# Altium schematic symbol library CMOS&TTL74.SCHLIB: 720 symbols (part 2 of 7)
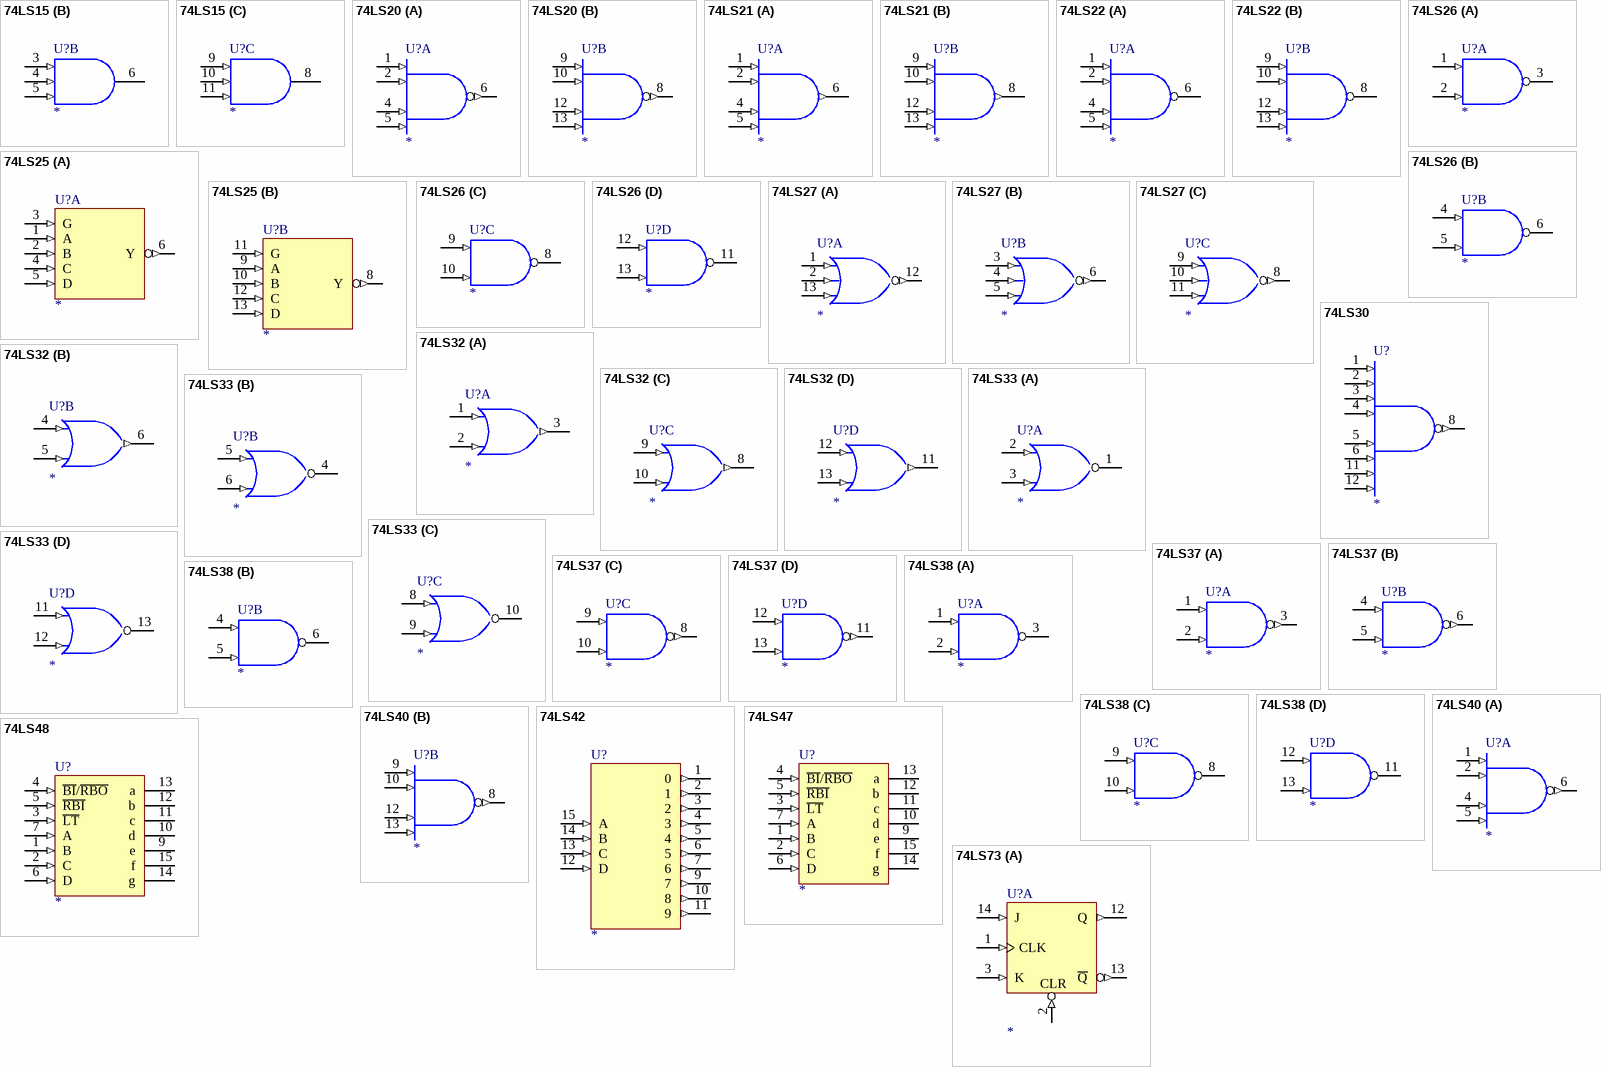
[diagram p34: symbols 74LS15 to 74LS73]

## 74LS30
designator U?
8-Input Positive-NAND Gate
footprint DIP-14
simulation model 74LS30 (SIMCODE)
pins: 1 A (in), 2 B (in), 3 C (in), 4 D (in), 5 E (in), 6 F (in), 7 GND (power) hidden to GND, 8 Y (out), 11 G (in), 12 H (in), 14 VCC (power) hidden to VCC
1 alternate drawing of the same symbol

## 74LS32
designator U?
Quad 2-Input Positive-OR Gate
footprint DIP-14
simulation model 74LS32 (SIMCODE)
part A pins: 1 A (in), 2 B (in), 3 Y (out), 7 GND (power) hidden to GND, 14 VCC (power) hidden to VCC
part B pins: 4 A (in), 5 B (in), 6 Y (out), 7 GND (power) hidden to GND, 14 VCC (power) hidden to VCC
part C pins: 7 GND (power) hidden to GND, 8 Y (out), 9 A (in), 10 B (in), 14 VCC (power) hidden to VCC
part D pins: 7 GND (power) hidden to GND, 11 Y (out), 12 A (in), 13 B (in), 14 VCC (power) hidden to VCC
1 alternate drawing of the same symbol

## 74LS33
designator U?
Quad 2-Input Positive-NOR Buffer with Open-Collector Output
footprint DIP-14
simulation model 74LS33 (SIMCODE)
part A pins: 1 Y (oc), 2 A (in), 3 B (in), 7 GND (power) hidden to GND, 14 VCC (power) hidden to VCC
part B pins: 4 Y (oc), 5 A (in), 6 B (in), 7 GND (power) hidden to GND, 14 VCC (power) hidden to VCC
part C pins: 7 GND (power) hidden to GND, 8 A (in), 9 B (in), 10 Y (oc), 14 VCC (power) hidden to VCC
part D pins: 7 GND (power) hidden to GND, 11 A (in), 12 B (in), 13 Y (oc), 14 VCC (power) hidden to VCC
1 alternate drawing of the same symbol

## 74LS37
designator U?
Quad 2-Input Positive-NAND Buffer
footprint DIP-14
simulation model 74LS37 (SIMCODE)
part A pins: 1 A (in), 2 B (in), 3 Y (out), 7 GND (power) hidden to GND, 14 VCC (power) hidden to VCC
part B pins: 4 A (in), 5 B (in), 6 Y (out), 7 GND (power) hidden to GND, 14 VCC (power) hidden to VCC
part C pins: 7 GND (power) hidden to GND, 8 Y (out), 9 A (in), 10 B (in), 14 VCC (power) hidden to VCC
part D pins: 7 GND (power) hidden to GND, 11 Y (out), 12 A (in), 13 B (in), 14 VCC (power) hidden to VCC
1 alternate drawing of the same symbol

## 74LS38
designator U?
Quad 2-Input Positive-NAND Buffer with Open-Collector Output
footprint DIP-14
simulation model 74LS38 (SIMCODE)
part A pins: 1 A (in), 2 B (in), 3 Y (oc), 7 GND (power) hidden to GND, 14 VCC (power) hidden to VCC
part B pins: 4 A (in), 5 B (in), 6 Y (oc), 7 GND (power) hidden to GND, 14 VCC (power) hidden to VCC
part C pins: 7 GND (power) hidden to GND, 8 Y (oc), 9 A (in), 10 B (in), 14 VCC (power) hidden to VCC
part D pins: 7 GND (power) hidden to GND, 11 Y (oc), 12 A (in), 13 B (in), 14 VCC (power) hidden to VCC
1 alternate drawing of the same symbol

## 74LS40
designator U?
Dual 4-Input Positive-NAND Buffer
footprint DIP-14
simulation model 74LS40 (SIMCODE)
part A pins: 1 A (in), 2 B (in), 4 C (in), 5 D (in), 6 Y (out), 7 GND (power) hidden to GND, 14 VCC (power) hidden to VCC
part B pins: 7 GND (power) hidden to GND, 8 Y (out), 9 A (in), 10 B (in), 12 C (in), 13 D (in), 14 VCC (power) hidden to VCC
2 alternate drawings of the same symbol

## 74LS42
designator U?
4-Line BCD to 10-Line Decimal Decoder
footprint DIP-16
simulation model 74LS42 (SIMCODE)
pins: 1 0 (out), 2 1 (out), 3 2 (out), 4 3 (out), 5 4 (out), 6 5 (out), 7 6 (out), 8 GND (power) hidden to GND, 9 7 (out), 10 8 (out), 11 9 (out), 12 D (in), 13 C (in), 14 B (in), 15 A (in), 16 VCC (power) hidden to VCC
1 alternate drawing of the same symbol

## 74LS47
designator U?
BCD-to-Seven-Segment Decoder/Driver
footprint DIP-16
simulation model 74LS47 (SIMCODE)
pins: 1 B (in), 2 C (in), 3 ~{LT} (in), 4 ~{BI}/~{RBO} (in), 5 ~{RBI} (in), 6 D (in), 7 A (in), 8 GND (power) hidden to GND, 9 e (oc), 10 d (oc), 11 c (oc), 12 b (oc), 13 a (oc), 14 g (oc), 15 f (oc), 16 VCC (power) hidden to VCC
1 alternate drawing of the same symbol

## 74LS48
designator U?
BCD-to-Seven-Segment Decoder/Driver
footprint DIP-16
simulation model 74LS48 (SIMCODE)
pins: 1 B (in), 2 C (in), 3 ~{LT} (in), 4 ~{BI}/~{RBO} (in), 5 ~{RBI} (in), 6 D (in), 7 A (in), 8 GND (power) hidden to GND, 9 e (oc), 10 d (oc), 11 c (oc), 12 b (oc), 13 a (oc), 14 g (oc), 15 f (oc), 16 VCC (power) hidden to VCC
1 alternate drawing of the same symbol

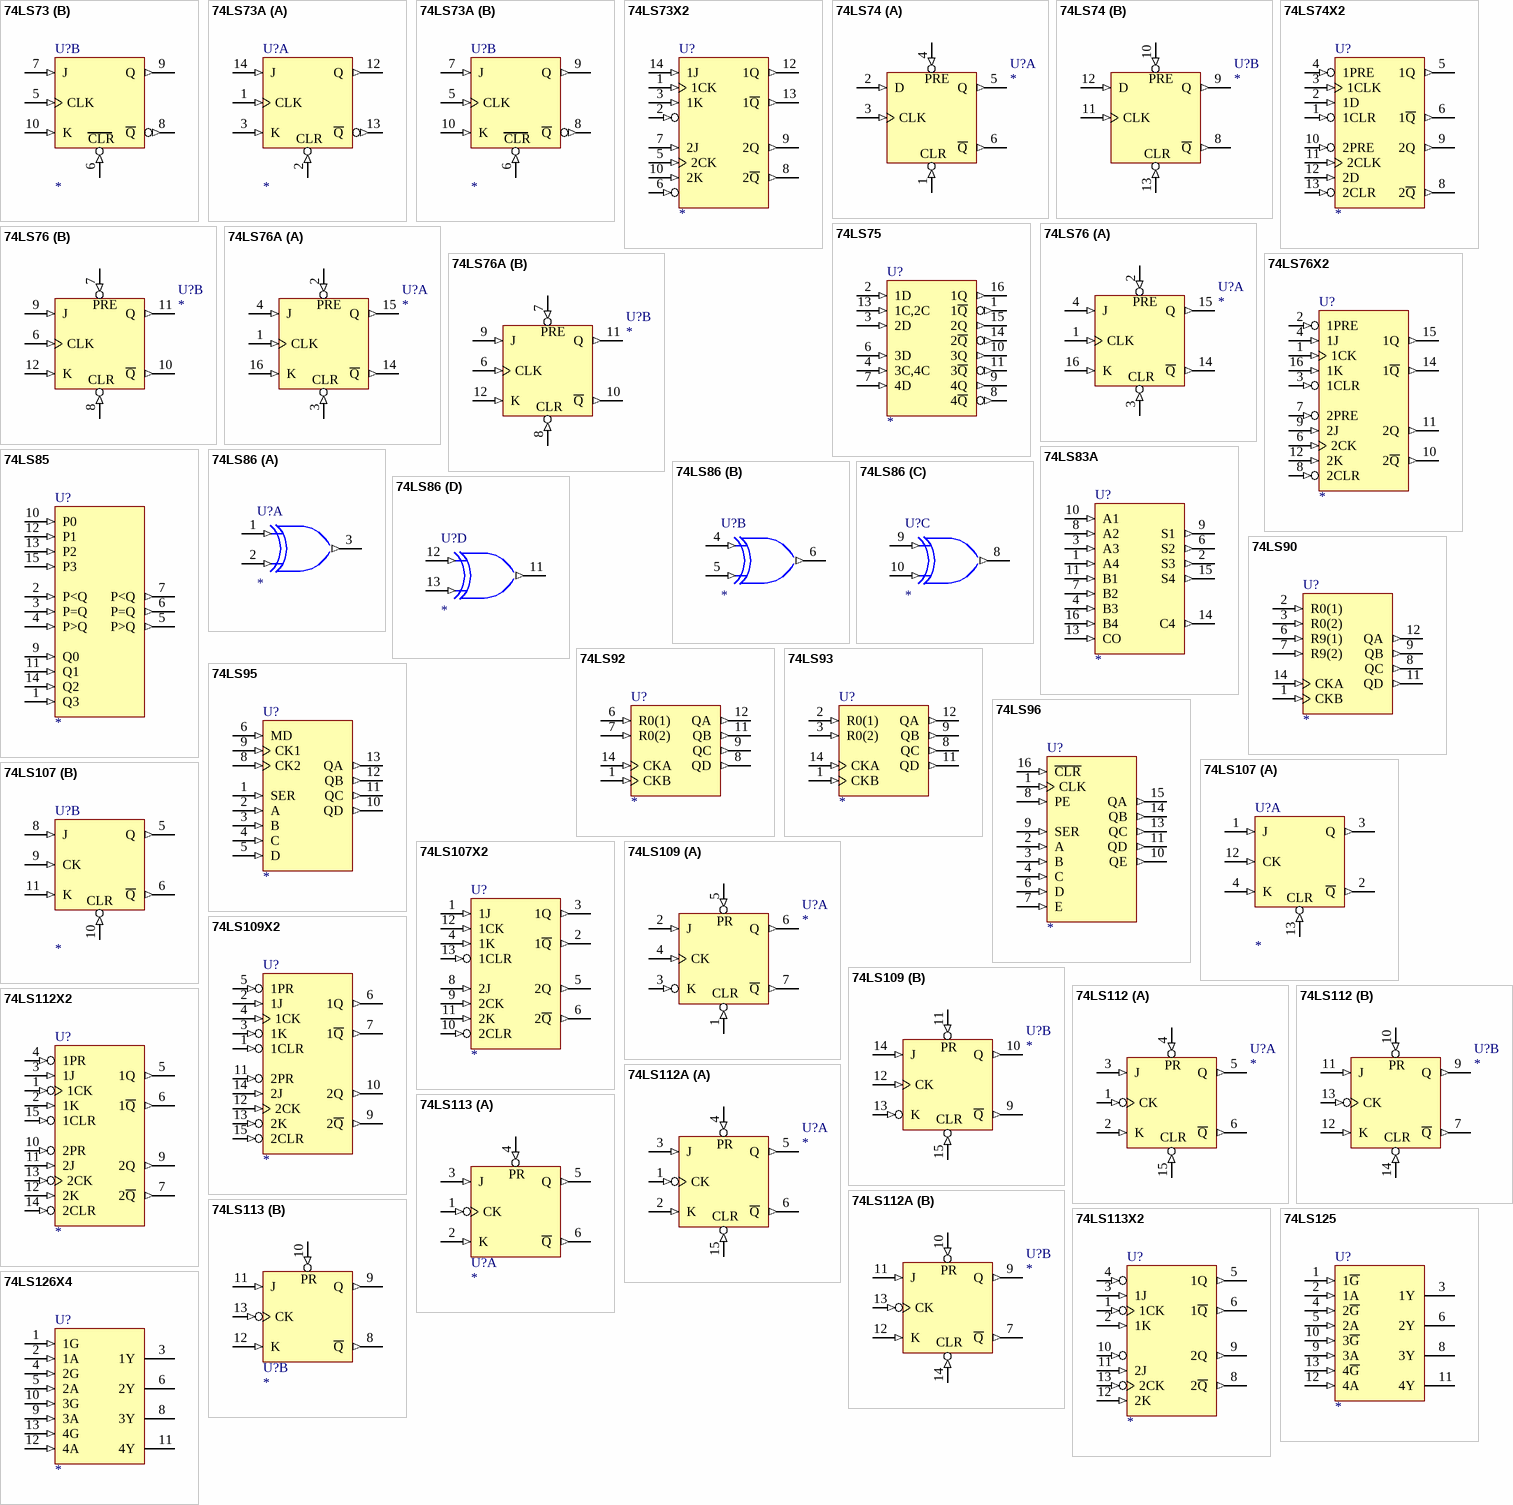
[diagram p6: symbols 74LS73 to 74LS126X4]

## 74LS73
designator U?
Dual J-K Flip-Flop with Clear
footprint DIP-14
simulation model 74LS73 (SIMCODE)
part A pins: 1 CLK (in), 2 ~{CLR} (in), 3 K (in), 4 VCC (power) hidden to VCC, 11 GND (power) hidden to GND, 12 Q (out), 13 ~{Q} (out), 14 J (in)
part B pins: 4 VCC (power) hidden to VCC, 5 CLK (in), 6 ~{CLR} (in), 7 J (in), 8 ~{Q} (out), 9 Q (out), 10 K (in), 11 GND (power) hidden to GND
1 alternate drawing of the same symbol

## 74LS73A
designator U?
Dual J-K Flip-Flop with Clear
footprint DIP-14
simulation model 74LS73A (SIMCODE)
part A pins: 1 CLK (in), 2 ~{CLR} (in), 3 K (in), 4 VCC (power) hidden to VCC, 11 GND (power) hidden to GND, 12 Q (out), 13 ~{Q} (out), 14 J (in)
part B pins: 4 VCC (power) hidden to VCC, 5 CLK (in), 6 ~{CLR} (in), 7 J (in), 8 ~{Q} (out), 9 Q (out), 10 K (in), 11 GND (power) hidden to GND
1 alternate drawing of the same symbol

## 74LS73X2
designator U?
Dual J-K Flip-Flop with Clear
footprint DIP-14
simulation model 74LS73X2 (SIMCODE)
pins: 1 1CK (in), 2 1CLR (in), 3 1K (in), 4 VCC (power) hidden to VCC, 5 2CK (in), 6 2CLR (in), 7 2J (in), 8 2~{Q} (out), 9 2Q (out), 10 2K (in), 11 GND (power) hidden to GND, 12 1Q (out), 13 1~{Q} (out), 14 1J (in)
1 alternate drawing of the same symbol

## 74LS74
designator U?
Dual D-Type Positive-Edge-Triggered Flip-Flop with Clear and Preset
footprint DIP-14
simulation model 74LS74 (SIMCODE)
part A pins: 1 ~{CLR} (in), 2 D (in), 3 CLK (in), 4 ~{PRE} (in), 5 Q (out), 6 ~{Q} (out), 7 GND (power) hidden to GND, 14 VCC (power) hidden to VCC
part B pins: 7 GND (power) hidden to GND, 8 ~{Q} (out), 9 Q (out), 10 ~{PRE} (in), 11 CLK (in), 12 D (in), 13 ~{CLR} (in), 14 VCC (power) hidden to VCC
1 alternate drawing of the same symbol

## 74LS74X2
designator U?
Dual D-Type Positive-Edge-Triggered Flip-Flop with Clear and Preset
footprint DIP-14
simulation model 74LS74X2 (SIMCODE)
pins: 1 1CLR (in), 2 1D (in), 3 1CLK (in), 4 1PRE (in), 5 1Q (out), 6 1~{Q} (out), 7 GND (power) hidden to GND, 8 2~{Q} (out), 9 2Q (out), 10 2PRE (in), 11 2CLK (in), 12 2D (in), 13 2CLR (in), 14 VCC (power) hidden to VCC
1 alternate drawing of the same symbol

## 74LS75
designator U?
4-Bit Bistable Latch
footprint DIP-16
simulation model 74LS75 (SIMCODE)
pins: 1 1~{Q} (out), 2 1D (in), 3 2D (in), 4 3C,4C (in), 5 VCC (power) hidden to VCC, 6 3D (in), 7 4D (in), 8 4~{Q} (out), 9 4Q (out), 10 3Q (out), 11 3~{Q} (out), 12 GND (power) hidden to GND, 13 1C,2C (in), 14 2~{Q} (out), 15 2Q (out), 16 1Q (out)
1 alternate drawing of the same symbol

## 74LS76
designator U?
Dual J-K Flip-Flop with Clear and Preset
footprint DIP-16
simulation model 74LS76 (SIMCODE)
part A pins: 1 CLK (in), 2 ~{PRE} (in), 3 ~{CLR} (in), 4 J (in), 5 VCC (power) hidden to VCC, 13 GND (power) hidden to GND, 14 ~{Q} (out), 15 Q (out), 16 K (in)
part B pins: 5 VCC (power) hidden to VCC, 6 CLK (in), 7 ~{PRE} (in), 8 ~{CLR} (in), 9 J (in), 10 ~{Q} (out), 11 Q (out), 12 K (in), 13 GND (power) hidden to GND
1 alternate drawing of the same symbol

## 74LS76A
designator U?
Dual J-K Flip-Flop with Clear and Preset
footprint DIP-16
simulation model 74LS76A (SIMCODE)
part A pins: 1 CLK (in), 2 ~{PRE} (in), 3 ~{CLR} (in), 4 J (in), 5 VCC (power) hidden to VCC, 13 GND (power) hidden to GND, 14 ~{Q} (out), 15 Q (out), 16 K (in)
part B pins: 5 VCC (power) hidden to VCC, 6 CLK (in), 7 ~{PRE} (in), 8 ~{CLR} (in), 9 J (in), 10 ~{Q} (out), 11 Q (out), 12 K (in), 13 GND (power) hidden to GND
1 alternate drawing of the same symbol

## 74LS76X2
designator U?
Dual J-K Flip-Flop with Clear and Preset
footprint DIP-16
simulation model 74LS76X2 (SIMCODE)
pins: 1 1CK (in), 2 1PRE (in), 3 1CLR (in), 4 1J (in), 5 VCC (power) hidden to VCC, 6 2CK (in), 7 2PRE (in), 8 2CLR (in), 9 2J (in), 10 2~{Q} (out), 11 2Q (out), 12 2K (in), 13 GND (power) hidden to GND, 14 1~{Q} (out), 15 1Q (out), 16 1K (in)
1 alternate drawing of the same symbol

## 74LS83A
designator U?
4-Bit Binary Full Adder with Fast Carry
footprint DIP-16
simulation model 74LS83A (SIMCODE)
pins: 1 A4 (in), 2 S3 (out), 3 A3 (in), 4 B3 (in), 5 VCC (power) hidden to VCC, 6 S2 (out), 7 B2 (in), 8 A2 (in), 9 S1 (out), 10 A1 (in), 11 B1 (in), 12 GND (power) hidden to GND, 13 CO (in), 14 C4 (out), 15 S4 (out), 16 B4 (in)
1 alternate drawing of the same symbol

## 74LS85
designator U?
4-Bit Magnitude Comparator
footprint DIP-16
simulation model 74LS85 (SIMCODE)
pins: 1 Q3 (in), 2 P<Q (in), 3 P=Q (in), 4 P>Q (in), 5 P>Q (out), 6 P=Q (out), 7 P<Q (out), 8 GND (power) hidden to GND, 9 Q0 (in), 10 P0 (in), 11 Q1 (in), 12 P1 (in), 13 P2 (in), 14 Q2 (in), 15 P3 (in), 16 VCC (power) hidden to VCC
1 alternate drawing of the same symbol

## 74LS86
designator U?
Quad Exclusive-OR Gate
footprint DIP-14
simulation model 74LS86 (SIMCODE)
part A pins: 1 A (in), 2 B (in), 3 Y (out), 7 GND (power) hidden to GND, 14 VCC (power) hidden to VCC
part B pins: 4 A (in), 5 B (in), 6 Y (out), 7 GND (power) hidden to GND, 14 VCC (power) hidden to VCC
part C pins: 7 GND (power) hidden to GND, 8 Y (out), 9 A (in), 10 B (in), 14 VCC (power) hidden to VCC
part D pins: 7 GND (power) hidden to GND, 11 Y (out), 12 A (in), 13 B (in), 14 VCC (power) hidden to VCC
1 alternate drawing of the same symbol

## 74LS90
designator U?
Binary Counter
footprint DIP-14
simulation model 74LS90 (SIMCODE)
pins: 1 CKB (in), 2 R0(1) (in), 3 R0(2) (in), 5 VCC (power) hidden to VCC, 6 R9(1) (in), 7 R9(2) (in), 8 QC (out), 9 QB (out), 10 GND (power) hidden to GND, 11 QD (out), 12 QA (out), 14 CKA (in)
1 alternate drawing of the same symbol

## 74LS92
designator U?
Divide-by-Twelve Counter
footprint DIP-14
simulation model 74LS92 (SIMCODE)
pins: 1 CKB (in), 5 VCC (power) hidden to VCC, 6 R0(1) (in), 7 R0(2) (in), 8 QD (out), 9 QC (out), 10 GND (power) hidden to GND, 11 QB (out), 12 QA (out), 14 CKA (in)
1 alternate drawing of the same symbol

## 74LS93
designator U?
4-Bit Binary Counter
footprint DIP-14
simulation model 74LS93 (SIMCODE)
pins: 1 CKB (in), 2 R0(1) (in), 3 R0(2) (in), 5 VCC (power) hidden to VCC, 8 QC (out), 9 QB (out), 10 GND (power) hidden to GND, 11 QD (out), 12 QA (out), 14 CKA (in)
1 alternate drawing of the same symbol

## 74LS95
designator U?
4-Bit Parallel-Access Shift Register
footprint DIP-14
simulation model 74LS95 (SIMCODE)
pins: 1 SER (in), 2 A (in), 3 B (in), 4 C (in), 5 D (in), 6 MD (in), 7 GND (power) hidden to GND, 8 CK2 (in), 9 CK1 (in), 10 QD (out), 11 QC (out), 12 QB (out), 13 QA (out), 14 VCC (power) hidden to VCC
1 alternate drawing of the same symbol

## 74LS96
designator U?
5-Bit Shift Register
footprint DIP-16
simulation model 74LS96 (SIMCODE)
pins: 1 CLK (in), 2 A (in), 3 B (in), 4 C (in), 5 VCC (power) hidden to VCC, 6 D (in), 7 E (in), 8 PE (in), 9 SER (in), 10 QE (out), 11 QD (out), 12 GND (power) hidden to GND, 13 QC (out), 14 QB (out), 15 QA (out), 16 ~{CLR} (in)
1 alternate drawing of the same symbol

## 74LS107
designator U?
Dual J-K Flip-Flops with Clear
footprint DIP-14
simulation model 74LS107 (SIMCODE)
part A pins: 1 J (in), 2 ~{Q} (out), 3 Q (out), 4 K (in), 7 GND (power) hidden to GND, 12 CK (in), 13 CLR (in), 14 VCC (power) hidden to VCC
part B pins: 5 Q (out), 6 ~{Q} (out), 7 GND (power) hidden to GND, 8 J (in), 9 CK (in), 10 CLR (in), 11 K (in), 14 VCC (power) hidden to VCC
1 alternate drawing of the same symbol

## 74LS107X2
designator U?
Dual J-K Flip-Flops with Clear
footprint DIP-14
simulation model 74LS107X2 (SIMCODE)
pins: 1 1J (in), 2 1~{Q} (out), 3 1Q (out), 4 1K (in), 5 2Q (out), 6 2~{Q} (out), 7 GND (power) hidden to GND, 8 2J (in), 9 2CK (in), 10 2CLR (in), 11 2K (in), 12 1CK (in), 13 1CLR (in), 14 VCC (power) hidden to VCC
1 alternate drawing of the same symbol

## 74LS109
designator U?
Dual J-~K Positive-Edge-Triggered Flip Flop with Preset and Clear
footprint DIP-16
simulation model 74LS109 (SIMCODE)
part A pins: 1 CLR (in), 2 J (in), 3 K (in), 4 CK (in), 5 PR (in), 6 Q (out), 7 ~{Q} (out), 8 GND (power) hidden to GND, 16 VCC (power) hidden to VCC
part B pins: 8 GND (power) hidden to GND, 9 ~{Q} (out), 10 Q (out), 11 PR (in), 12 CK (in), 13 K (in), 14 J (in), 15 CLR (in), 16 VCC (power) hidden to VCC
1 alternate drawing of the same symbol

## 74LS109X2
designator U?
Dual J-~K Positive-Edge-Triggered Flip Flop with Preset and Clear
footprint DIP-16
simulation model 74LS109X2 (SIMCODE)
pins: 1 1CLR (in), 2 1J (in), 3 1K (in), 4 1CK (in), 5 1PR (in), 6 1Q (out), 7 1~{Q} (out), 8 GND (power) hidden to GND, 9 2~{Q} (out), 10 2Q (out), 11 2PR (in), 12 2CK (in), 13 2K (in), 14 2J (in), 15 2CLR (in), 16 VCC (power) hidden to VCC
1 alternate drawing of the same symbol

## 74LS112
designator U?
Dual J-K Negative-Edge-Triggered Flip-Flop with Clear and Preset
footprint DIP-16
simulation model 74LS112 (SIMCODE)
part A pins: 1 CK (in), 2 K (in), 3 J (in), 4 PR (in), 5 Q (out), 6 ~{Q} (out), 8 GND (power) hidden to GND, 15 CLR (in), 16 VCC (power) hidden to VCC
part B pins: 7 ~{Q} (out), 8 GND (power) hidden to GND, 9 Q (out), 10 PR (in), 11 J (in), 12 K (in), 13 CK (in), 14 CLR (in), 16 VCC (power) hidden to VCC
1 alternate drawing of the same symbol

## 74LS112A
designator U?
Dual J-K Negative-Edge-Triggered Flip-Flop with Clear and Preset
footprint DIP-16
simulation model 74LS112A (SIMCODE)
part A pins: 1 CK (in), 2 K (in), 3 J (in), 4 PR (in), 5 Q (out), 6 ~{Q} (out), 8 GND (power) hidden to GND, 15 CLR (in), 16 VCC (power) hidden to VCC
part B pins: 7 ~{Q} (out), 8 GND (power) hidden to GND, 9 Q (out), 10 PR (in), 11 J (in), 12 K (in), 13 CK (in), 14 CLR (in), 16 VCC (power) hidden to VCC
1 alternate drawing of the same symbol

## 74LS112X2
designator U?
Dual J-K Negative-Edge-Triggered Flip-Flop with Clear and Preset
footprint DIP-16
simulation model 74LS112X2 (SIMCODE)
pins: 1 1CK (in), 2 1K (in), 3 1J (in), 4 1PR (in), 5 1Q (out), 6 1~{Q} (out), 7 2~{Q} (out), 8 GND (power) hidden to GND, 9 2Q (out), 10 2PR (in), 11 2J (in), 12 2K (in), 13 2CK (in), 14 2CLR (in), 15 1CLR (in), 16 VCC (power) hidden to VCC
1 alternate drawing of the same symbol

## 74LS113
designator U?
Dual J-K Negative-Edge-Triggered Flip-Flop with Preset
footprint DIP-14
simulation model 74LS113 (SIMCODE)
part A pins: 1 CK (in), 2 K (in), 3 J (in), 4 PR (in), 5 Q (out), 6 ~{Q} (out), 7 GND (power) hidden to GND, 14 VCC (power) hidden to VCC
part B pins: 7 GND (power) hidden to GND, 8 ~{Q} (out), 9 Q (out), 10 PR (in), 11 J (in), 12 K (in), 13 CK (in), 14 VCC (power) hidden to VCC
1 alternate drawing of the same symbol

## 74LS113X2
designator U?
Dual J-K Negative-Edge-Triggered Flip-Flop with Preset
footprint DIP-14
simulation model 74LS113X2 (SIMCODE)
pins: 1 1CK (in), 2 1K (in), 3 1J (in), 4 1PR (in), 5 1Q (out), 6 1~{Q} (out), 7 GND (power) hidden to GND, 8 2~{Q} (out), 9 2Q (out), 10 2PR (in), 11 2J (in), 12 2K (in), 13 2CK (in), 14 VCC (power) hidden to VCC
1 alternate drawing of the same symbol

## 74LS125
designator U?
Quad Bus Buffer Gate with 3-State Output
footprint DIP-14
simulation model 74LS125 (SIMCODE)
pins: 1 1~{G} (in), 2 1A (in), 3 1Y (hiz), 4 2~{G} (in), 5 2A (in), 6 2Y (hiz), 7 GND (power) hidden to GND, 8 3Y (hiz), 9 3A (in), 10 3~{G} (in), 11 4Y (hiz), 12 4A (in), 13 4~{G} (in), 14 VCC (power) hidden to VCC
1 alternate drawing of the same symbol

## 74LS126X4
designator U?
Quad Bus Buffer Gate with 3-State Output
footprint DIP-14
simulation model 74LS126X4 (SIMCODE)
pins: 1 1G (in), 2 1A (in), 3 1Y (hiz), 4 2G (in), 5 2A (in), 6 2Y (hiz), 7 GND (power) hidden to GND, 8 3Y (hiz), 9 3A (in), 10 3G (in), 11 4Y (hiz), 12 4A (in), 13 4G (in), 14 VCC (power) hidden to VCC
1 alternate drawing of the same symbol

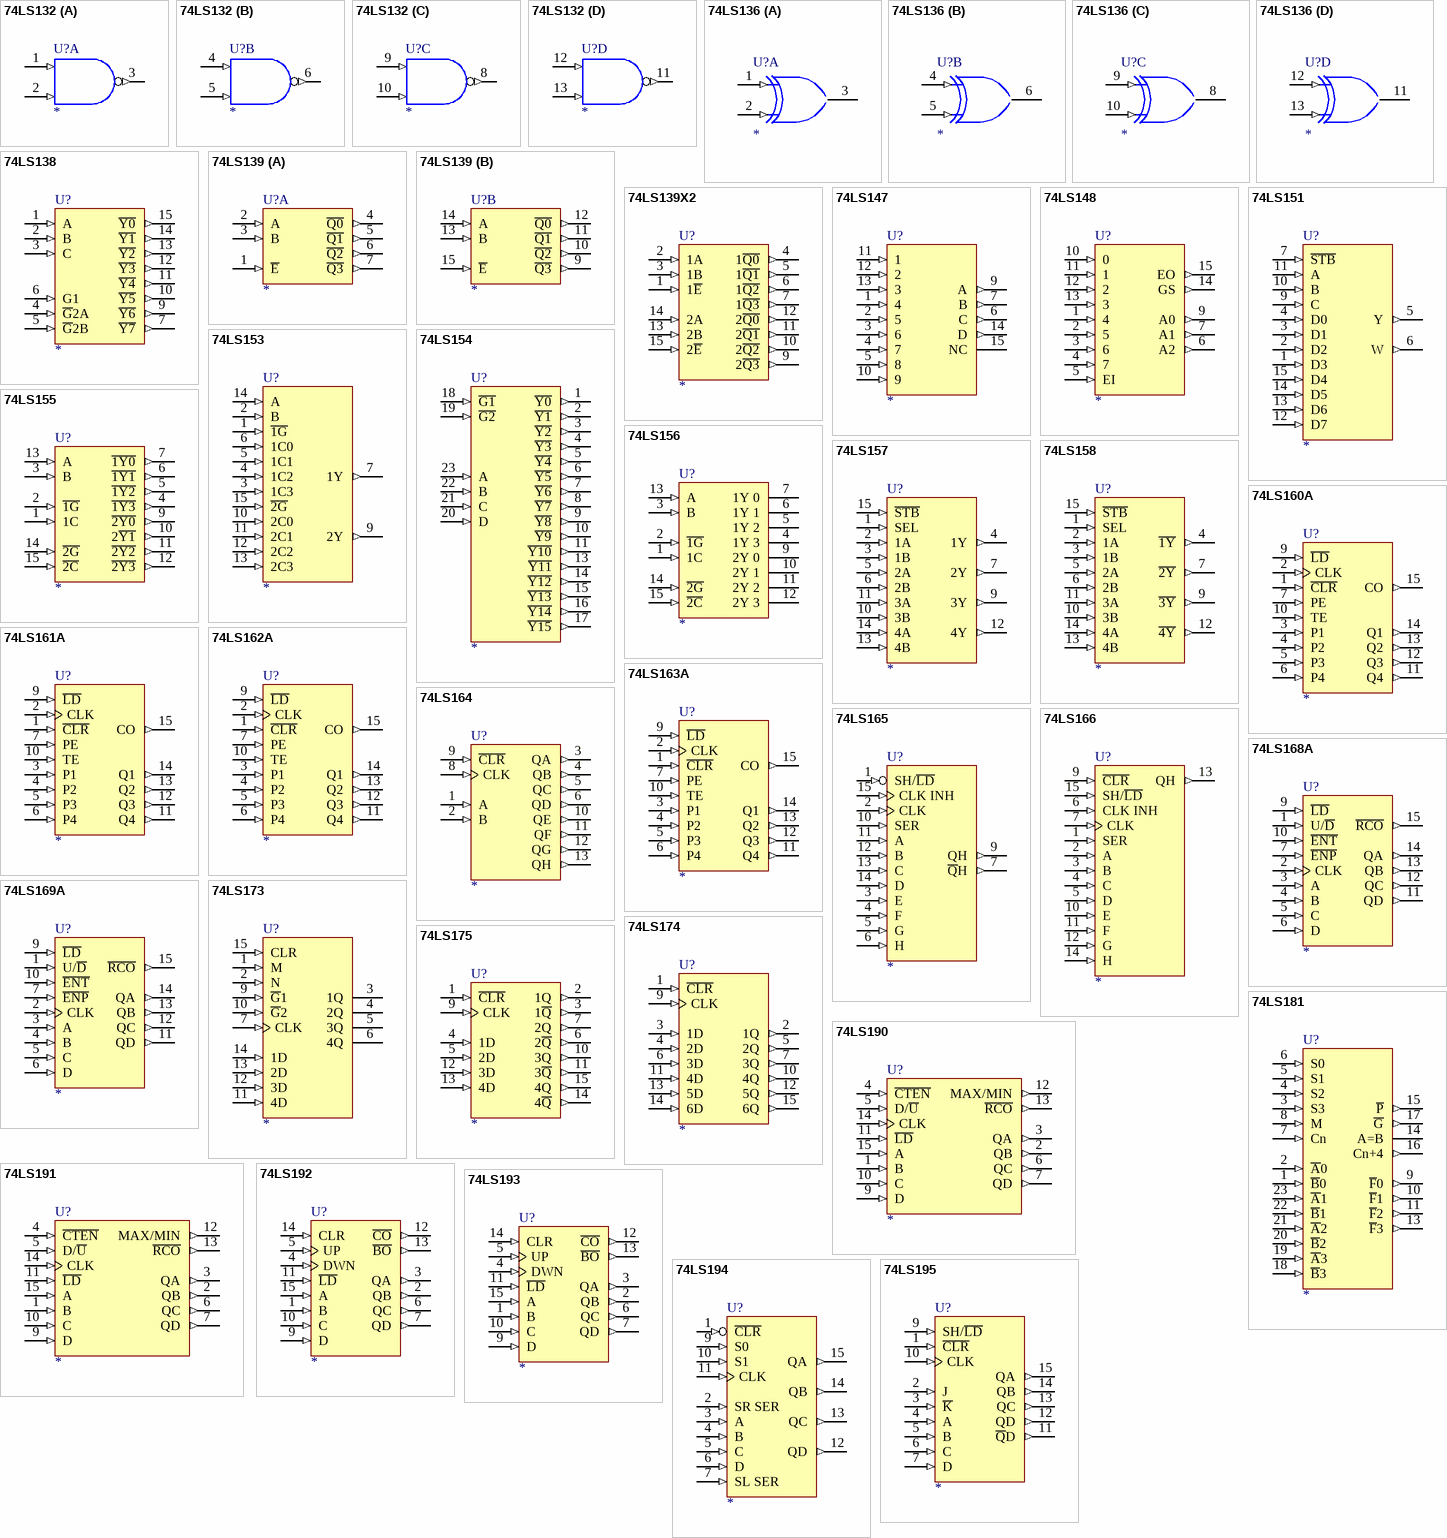
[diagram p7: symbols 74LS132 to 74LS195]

## 74LS132
designator U?
Quad Positive-NAND Gate with Schmitt-Trigger Input
footprint DIP-14
simulation model 74LS132 (SIMCODE)
part A pins: 1 A (in), 2 B (in), 3 Y (out), 7 GND (power) hidden to GND, 14 VCC (power) hidden to VCC
part B pins: 4 A (in), 5 B (in), 6 Y (out), 7 GND (power) hidden to GND, 14 VCC (power) hidden to VCC
part C pins: 7 GND (power) hidden to GND, 8 Y (out), 9 A (in), 10 B (in), 14 VCC (power) hidden to VCC
part D pins: 7 GND (power) hidden to GND, 11 Y (out), 12 A (in), 13 B (in), 14 VCC (power) hidden to VCC
1 alternate drawing of the same symbol

## 74LS136
designator U?
Quad 2-Input Exclusive-OR Gate with Open-Collector Output
footprint DIP-14
simulation model 74LS136 (SIMCODE)
part A pins: 1 A (in), 2 B (in), 3 Y (oc), 7 GND (power) hidden to GND, 14 VCC (power) hidden to VCC
part B pins: 4 A (in), 5 B (in), 6 Y (oc), 7 GND (power) hidden to GND, 14 VCC (power) hidden to VCC
part C pins: 7 GND (power) hidden to GND, 8 Y (oc), 9 A (in), 10 B (in), 14 VCC (power) hidden to VCC
part D pins: 7 GND (power) hidden to GND, 11 Y (oc), 12 A (in), 13 B (in), 14 VCC (power) hidden to VCC
1 alternate drawing of the same symbol

## 74LS138
designator U?
3-Line to 8-Line Decoder/Demultiplexer
footprint DIP-16
simulation model 74LS138 (SIMCODE)
pins: 1 A (in), 2 B (in), 3 C (in), 4 ~{G}2A (in), 5 ~{G}2B (in), 6 G1 (in), 7 ~{Y7} (out), 8 GND (power) hidden to GND, 9 ~{Y6} (out), 10 ~{Y5} (out), 11 ~{Y4} (out), 12 ~{Y3} (out), 13 ~{Y2} (out), 14 ~{Y1} (out), 15 ~{Y0} (out), 16 VCC (power) hidden to VCC
1 alternate drawing of the same symbol

## 74LS139
designator U?
Dual 2-Line to 4-Line Decoder/Demultiplexer
footprint DIP-16
simulation model 74LS139 (SIMCODE)
part A pins: 1 ~{E} (in), 2 A (in), 3 B (in), 4 ~{Q0} (out), 5 ~{Q1} (out), 6 ~{Q2} (out), 7 ~{Q3} (out), 8 GND (power) hidden to GND, 16 VCC (power) hidden to VCC
part B pins: 8 GND (power) hidden to GND, 9 ~{Q3} (out), 10 ~{Q2} (out), 11 ~{Q1} (out), 12 ~{Q0} (out), 13 B (in), 14 A (in), 15 ~{E} (in), 16 VCC (power) hidden to VCC
1 alternate drawing of the same symbol

## 74LS139X2
designator U?
Dual 2-Line to 4-Line Decoder/Demultiplexer
footprint DIP-16
simulation model 74LS139X2 (SIMCODE)
pins: 1 1~{E} (in), 2 1A (in), 3 1B (in), 4 1~{Q0} (out), 5 1~{Q1} (out), 6 1~{Q2} (out), 7 1~{Q3} (out), 8 GND (power) hidden to GND, 9 2~{Q3} (out), 10 2~{Q2} (out), 11 2~{Q1} (out), 12 2~{Q0} (out), 13 2B (in), 14 2A (in), 15 2~{E} (in), 16 VCC (power) hidden to VCC
1 alternate drawing of the same symbol

## 74LS147
designator U?
10-Line to 4-Line Priority Encoder
footprint DIP-16
simulation model 74LS147 (SIMCODE)
pins: 1 4 (in), 2 5 (in), 3 6 (in), 4 7 (in), 5 8 (in), 6 C (out), 7 B (out), 8 GND (power) hidden to GND, 9 A (out), 10 9 (in), 11 1 (in), 12 2 (in), 13 3 (in), 14 D (out), 15 NC, 16 VCC (power) hidden to VCC
1 alternate drawing of the same symbol

## 74LS148
designator U?
8-Line to 3-Line Priority Encoder
footprint DIP-16
simulation model 74LS148 (SIMCODE)
pins: 1 4 (in), 2 5 (in), 3 6 (in), 4 7 (in), 5 EI (in), 6 A2 (out), 7 A1 (out), 8 GND (power) hidden to GND, 9 A0 (out), 10 0 (in), 11 1 (in), 12 2 (in), 13 3 (in), 14 GS (out), 15 EO (out), 16 VCC (power) hidden to VCC
1 alternate drawing of the same symbol

## 74LS151
designator U?
1 of 8 Data Selector/Multiplexer
footprint DIP-16
simulation model 74LS151 (SIMCODE)
pins: 1 D3 (in), 2 D2 (in), 3 D1 (in), 4 D0 (in), 5 Y (out), 6 W (out), 7 ~{STB} (in), 8 GND (power) hidden to GND, 9 C (in), 10 B (in), 11 A (in), 12 D7 (in), 13 D6 (in), 14 D5 (in), 15 D4 (in), 16 VCC (power) hidden to VCC
1 alternate drawing of the same symbol

## 74LS153
designator U?
Dual 4-Line to 1-Line Data Selector/Multiplexer
footprint DIP-16
simulation model 74LS153 (SIMCODE)
pins: 1 ~{1G} (in), 2 B (in), 3 1C3 (in), 4 1C2 (in), 5 1C1 (in), 6 1C0 (in), 7 1Y (out), 8 GND (power) hidden to GND, 9 2Y (out), 10 2C0 (in), 11 2C1 (in), 12 2C2 (in), 13 2C3 (in), 14 A (in), 15 ~{2G} (in), 16 VCC (power) hidden to VCC
1 alternate drawing of the same symbol

## 74LS154
designator U?
4-Line to 16-Line Decoder/Demultiplexer
footprint DIP-24
simulation model 74LS154 (SIMCODE)
pins: 1 ~{Y0} (out), 2 ~{Y1} (out), 3 ~{Y2} (out), 4 ~{Y3} (out), 5 ~{Y4} (out), 6 ~{Y5} (out), 7 ~{Y6} (out), 8 ~{Y7} (out), 9 ~{Y8} (out), 10 ~{Y9} (out), 11 ~{Y10} (out), 12 GND (power) hidden to GND, 13 ~{Y11} (out), 14 ~{Y12} (out), 15 ~{Y13} (out), 16 ~{Y14} (out), 17 ~{Y15} (out), 18 ~{G1} (in), 19 ~{G2} (in), 20 D (in), 21 C (in), 22 B (in), 23 A (in), 24 VCC (power) hidden to VCC
1 alternate drawing of the same symbol

## 74LS155
designator U?
Dual 2-Line to 4-Line Decoder/Demultiplexer
footprint DIP-16
simulation model 74LS155 (SIMCODE)
pins: 1 1C (in), 2 ~{1G} (in), 3 B (in), 4 ~{1Y3} (out), 5 ~{1Y2} (out), 6 ~{1Y1} (out), 7 ~{1Y0} (out), 8 GND (power) hidden to GND, 9 ~{2Y0} (out), 10 2~{Y1} (out), 11 ~{2Y2} (out), 12 ~{2Y3} (out), 13 A (in), 14 ~{2G} (in), 15 ~{2C} (in), 16 VCC (power) hidden to VCC
1 alternate drawing of the same symbol

## 74LS156
designator U?
Dual 2-Line to 4-Line Decoder/Demultiplexer with Open-Collector Outputs
footprint DIP-16
simulation model 74LS156 (SIMCODE)
pins: 1 1C (in), 2 ~{1G} (in), 3 B (in), 4 1Y 3 (oc), 5 1Y 2 (oc), 6 1Y 1 (oc), 7 1Y 0 (oc), 8 GND (power) hidden to GND, 9 2Y 0 (oc), 10 2Y 1 (oc), 11 2Y 2 (oc), 12 2Y 3 (oc), 13 A (in), 14 ~{2G} (in), 15 ~{2C} (in), 16 VCC (power) hidden to VCC
1 alternate drawing of the same symbol

## 74LS157
designator U?
Quad 2-Line to 1-Line Data Selector/Multiplexer
footprint DIP-16
simulation model 74LS157 (SIMCODE)
pins: 1 SEL (in), 2 1A (in), 3 1B (in), 4 1Y (out), 5 2A (in), 6 2B (in), 7 2Y (out), 8 GND (power) hidden to GND, 9 3Y (out), 10 3B (in), 11 3A (in), 12 4Y (out), 13 4B (in), 14 4A (in), 15 ~{STB} (in), 16 VCC (power) hidden to VCC
1 alternate drawing of the same symbol

## 74LS158
designator U?
Quad 2-Line to 1-Line Data Selector/Multiplexer
footprint DIP-16
simulation model 74LS158 (SIMCODE)
pins: 1 SEL (in), 2 1A (in), 3 1B (in), 4 ~{1Y} (out), 5 2A (in), 6 2B (in), 7 ~{2Y} (out), 8 GND (power) hidden to GND, 9 ~{3Y} (out), 10 3B (in), 11 3A (in), 12 ~{4Y} (out), 13 4B (in), 14 4A (in), 15 ~{STB} (in), 16 VCC (power) hidden to VCC
1 alternate drawing of the same symbol

## 74LS160A
designator U?
Synchronous 4-Bit Decade Counter with Direct Clear
footprint DIP-16
simulation model 74LS160A (SIMCODE)
pins: 1 ~{CLR} (in), 2 CLK (in), 3 P1 (in), 4 P2 (in), 5 P3 (in), 6 P4 (in), 7 PE (in), 8 GND (power) hidden to GND, 9 ~{LD} (in), 10 TE (in), 11 Q4 (out), 12 Q3 (out), 13 Q2 (out), 14 Q1 (out), 15 CO (out), 16 VCC (power) hidden to VCC
1 alternate drawing of the same symbol

## 74LS161A
designator U?
Synchronous 4-Bit Binary Counter with Direct Clear
footprint DIP-16
simulation model 74LS161A (SIMCODE)
pins: 1 ~{CLR} (in), 2 CLK (in), 3 P1 (in), 4 P2 (in), 5 P3 (in), 6 P4 (in), 7 PE (in), 8 GND (power) hidden to GND, 9 ~{LD} (in), 10 TE (in), 11 Q4 (out), 12 Q3 (out), 13 Q2 (out), 14 Q1 (out), 15 CO (out), 16 VCC (power) hidden to VCC
1 alternate drawing of the same symbol

## 74LS162A
designator U?
Fully Synchronous 4-Bit Decade Counter
footprint DIP-16
simulation model 74LS162A (SIMCODE)
pins: 1 ~{CLR} (in), 2 CLK (in), 3 P1 (in), 4 P2 (in), 5 P3 (in), 6 P4 (in), 7 PE (in), 8 GND (power) hidden to GND, 9 ~{LD} (in), 10 TE (in), 11 Q4 (out), 12 Q3 (out), 13 Q2 (out), 14 Q1 (out), 15 CO (out), 16 VCC (power) hidden to VCC
1 alternate drawing of the same symbol

## 74LS163A
designator U?
Fully Synchronous 4-Bit Binary Counter
footprint DIP-16
simulation model 74LS163A (SIMCODE)
pins: 1 ~{CLR} (in), 2 CLK (in), 3 P1 (in), 4 P2 (in), 5 P3 (in), 6 P4 (in), 7 PE (in), 8 GND (power) hidden to GND, 9 ~{LD} (in), 10 TE (in), 11 Q4 (out), 12 Q3 (out), 13 Q2 (out), 14 Q1 (out), 15 CO (out), 16 VCC (power) hidden to VCC
1 alternate drawing of the same symbol

## 74LS164
designator U?
8-Bit Parallel-Out Serial Shift Register
footprint DIP-14
simulation model 74LS164 (SIMCODE)
pins: 1 A (in), 2 B (in), 3 QA (out), 4 QB (out), 5 QC (out), 6 QD (out), 7 GND (power) hidden to GND, 8 CLK (in), 9 ~{CLR} (in), 10 QE (out), 11 QF (out), 12 QG (out), 13 QH (out), 14 VCC (power) hidden to VCC
1 alternate drawing of the same symbol

## 74LS165
designator U?
Parallel-Load 8-Bit Shift Register
footprint DIP-16
simulation model 74LS165 (SIMCODE)
pins: 1 SH/~{LD} (in), 2 CLK (in), 3 E (in), 4 F (in), 5 G (in), 6 H (in), 7 ~{Q}H (out), 8 GND (power) hidden to GND, 9 QH (out), 10 SER (in), 11 A (in), 12 B (in), 13 C (in), 14 D (in), 15 CLK INH (in), 16 VCC (power) hidden to VCC
1 alternate drawing of the same symbol

## 74LS166
designator U?
Parallel-Load 8-Bit Shift Register
footprint DIP-16
simulation model 74LS166 (SIMCODE)
pins: 1 SER (in), 2 A (in), 3 B (in), 4 C (in), 5 D (in), 6 CLK INH (in), 7 CLK (in), 8 GND (power) hidden to GND, 9 ~{CLR} (in), 10 E (in), 11 F (in), 12 G (in), 13 QH (out), 14 H (in), 15 SH/~{LD} (in), 16 VCC (power) hidden to VCC
1 alternate drawing of the same symbol

## 74LS168A
designator U?
Synchronous 4-Bit Up/Down Decade Counter
footprint DIP-16
simulation model 74LS168A (SIMCODE)
pins: 1 U/~{D} (in), 2 CLK (in), 3 A (in), 4 B (in), 5 C (in), 6 D (in), 7 ~{ENP} (in), 8 GND (power) hidden to GND, 9 ~{LD} (in), 10 ~{ENT} (in), 11 QD (out), 12 QC (out), 13 QB (out), 14 QA (out), 15 ~{RCO} (out), 16 VCC (power) hidden to VCC
1 alternate drawing of the same symbol

## 74LS169A
designator U?
Synchronous 4-Bit Up/Down Decade Counter
footprint DIP-16
simulation model 74LS169A (SIMCODE)
pins: 1 U/~{D} (in), 2 CLK (in), 3 A (in), 4 B (in), 5 C (in), 6 D (in), 7 ~{ENP} (in), 8 GND (power) hidden to GND, 9 ~{LD} (in), 10 ~{ENT} (in), 11 QD (out), 12 QC (out), 13 QB (out), 14 QA (out), 15 ~{RCO} (out), 16 VCC (power) hidden to VCC
1 alternate drawing of the same symbol

## 74LS173
designator U?
4-Bit D-Type Register with 3-State Outputs
footprint DIP-16
simulation model 74LS173 (SIMCODE)
pins: 1 M (in), 2 N (in), 3 1Q (hiz), 4 2Q (hiz), 5 3Q (hiz), 6 4Q (hiz), 7 CLK (in), 8 GND (power) hidden to GND, 9 ~{G}1 (in), 10 ~{G}2 (in), 11 4D (in), 12 3D (in), 13 2D (in), 14 1D (in), 15 CLR (in), 16 VCC (power) hidden to VCC
1 alternate drawing of the same symbol

## 74LS174
designator U?
Hex D-Type Flip-Flop with Clear
footprint DIP-16
simulation model 74LS174 (SIMCODE)
pins: 1 ~{CLR} (in), 2 1Q (out), 3 1D (in), 4 2D (in), 5 2Q (out), 6 3D (in), 7 3Q (out), 8 GND (power) hidden to GND, 9 CLK (in), 10 4Q (out), 11 4D (in), 12 5Q (out), 13 5D (in), 14 6D (in), 15 6Q (out), 16 VCC (power) hidden to VCC
1 alternate drawing of the same symbol

## 74LS175
designator U?
Quad D-Type Flip-Flop with Clear
footprint DIP-16
simulation model 74LS175 (SIMCODE)
pins: 1 ~{CLR} (in), 2 1Q (out), 3 1~{Q} (out), 4 1D (in), 5 2D (in), 6 2~{Q} (out), 7 2Q (out), 8 GND (power) hidden to GND, 9 CLK (in), 10 3Q (out), 11 3~{Q} (out), 12 3D (in), 13 4D (in), 14 4~{Q} (out), 15 4Q (out), 16 VCC (power) hidden to VCC
1 alternate drawing of the same symbol

## 74LS181
designator U?
Arithmetic Logic Unit/Function Generator
footprint DIP-24
simulation model 74LS181 (SIMCODE)
pins: 1 ~{B}0 (in), 2 ~{A}0 (in), 3 S3 (in), 4 S2 (in), 5 S1 (in), 6 S0 (in), 7 Cn (in), 8 M (in), 9 ~{F}0 (out), 10 ~{F}1 (out), 11 ~{F}2 (out), 12 GND (power) hidden to GND, 13 ~{F}3 (out), 14 A=B (oc), 15 ~{P} (out), 16 Cn+4 (out), 17 ~{G} (out), 18 ~{B}3 (in), 19 ~{A}3 (in), 20 ~{B}2 (in), 21 ~{A}2 (in), 22 ~{B}1 (in), 23 ~{A}1 (in), 24 VCC (power) hidden to VCC
1 alternate drawing of the same symbol

## 74LS190
designator U?
Synchronous 4-Bit Up/Down Decade Counter with Down/Up Mode Control
footprint DIP-16
simulation model 74LS190 (SIMCODE)
pins: 1 B (in), 2 QB (out), 3 QA (out), 4 ~{CTEN} (in), 5 D/~{U} (in), 6 QC (out), 7 QD (out), 8 GND (power) hidden to GND, 9 D (in), 10 C (in), 11 ~{LD} (in), 12 MAX/MIN (out), 13 ~{RCO} (out), 14 CLK (in), 15 A (in), 16 VCC (power) hidden to VCC
1 alternate drawing of the same symbol

## 74LS191
designator U?
Synchronous 4-Bit Up/Down Binary Counter with Down/Up Mode Control
footprint DIP-16
simulation model 74LS191 (SIMCODE)
pins: 1 B (in), 2 QB (out), 3 QA (out), 4 ~{CTEN} (in), 5 D/~{U} (in), 6 QC (out), 7 QD (out), 8 GND (power) hidden to GND, 9 D (in), 10 C (in), 11 ~{LD} (in), 12 MAX/MIN (out), 13 ~{RCO} (out), 14 CLK (in), 15 A (in), 16 VCC (power) hidden to VCC
1 alternate drawing of the same symbol

## 74LS192
designator U?
Synchronous 4-Bit Up/Down Decade Counter (Dual Clock with Clear)
footprint DIP-16
simulation model 74LS192 (SIMCODE)
pins: 1 B (in), 2 QB (out), 3 QA (out), 4 DWN (in), 5 UP (in), 6 QC (out), 7 QD (out), 8 GND (power) hidden to GND, 9 D (in), 10 C (in), 11 ~{LD} (in), 12 ~{CO} (out), 13 ~{BO} (out), 14 CLR (in), 15 A (in), 16 VCC (power) hidden to VCC
1 alternate drawing of the same symbol

## 74LS193
designator U?
Synchronous 4-Bit Up/Down Binary Counter (Dual Clock with Clear)
footprint DIP-16
simulation model 74LS193 (SIMCODE)
pins: 1 B (in), 2 QB (out), 3 QA (out), 4 DWN (in), 5 UP (in), 6 QC (out), 7 QD (out), 8 GND (power) hidden to GND, 9 D (in), 10 C (in), 11 ~{LD} (in), 12 ~{CO} (out), 13 ~{BO} (out), 14 CLR (in), 15 A (in), 16 VCC (power) hidden to VCC
1 alternate drawing of the same symbol

## 74LS194
designator U?
4-Bit Bidirectional Universal Shift Register
footprint DIP-16
simulation model 74LS194 (SIMCODE)
pins: 1 ~{CLR} (in), 2 SR SER (in), 3 A (in), 4 B (in), 5 C (in), 6 D (in), 7 SL SER (in), 8 GND (power) hidden to GND, 9 S0 (in), 10 S1 (in), 11 CLK (in), 12 QD (out), 13 QC (out), 14 QB (out), 15 QA (out), 16 VCC (power) hidden to VCC
1 alternate drawing of the same symbol

## 74LS195
designator U?
4-Bit Parallel-Access Shift Register
footprint DIP-16
simulation model 74LS195 (SIMCODE)
pins: 1 ~{CLR} (in), 2 J (in), 3 ~{K} (in), 4 A (in), 5 B (in), 6 C (in), 7 D (in), 8 GND (power) hidden to GND, 9 SH/~{LD} (in), 10 CLK (in), 11 ~{Q}D (out), 12 QD (out), 13 QC (out), 14 QB (out), 15 QA (out), 16 VCC (power) hidden to VCC
1 alternate drawing of the same symbol

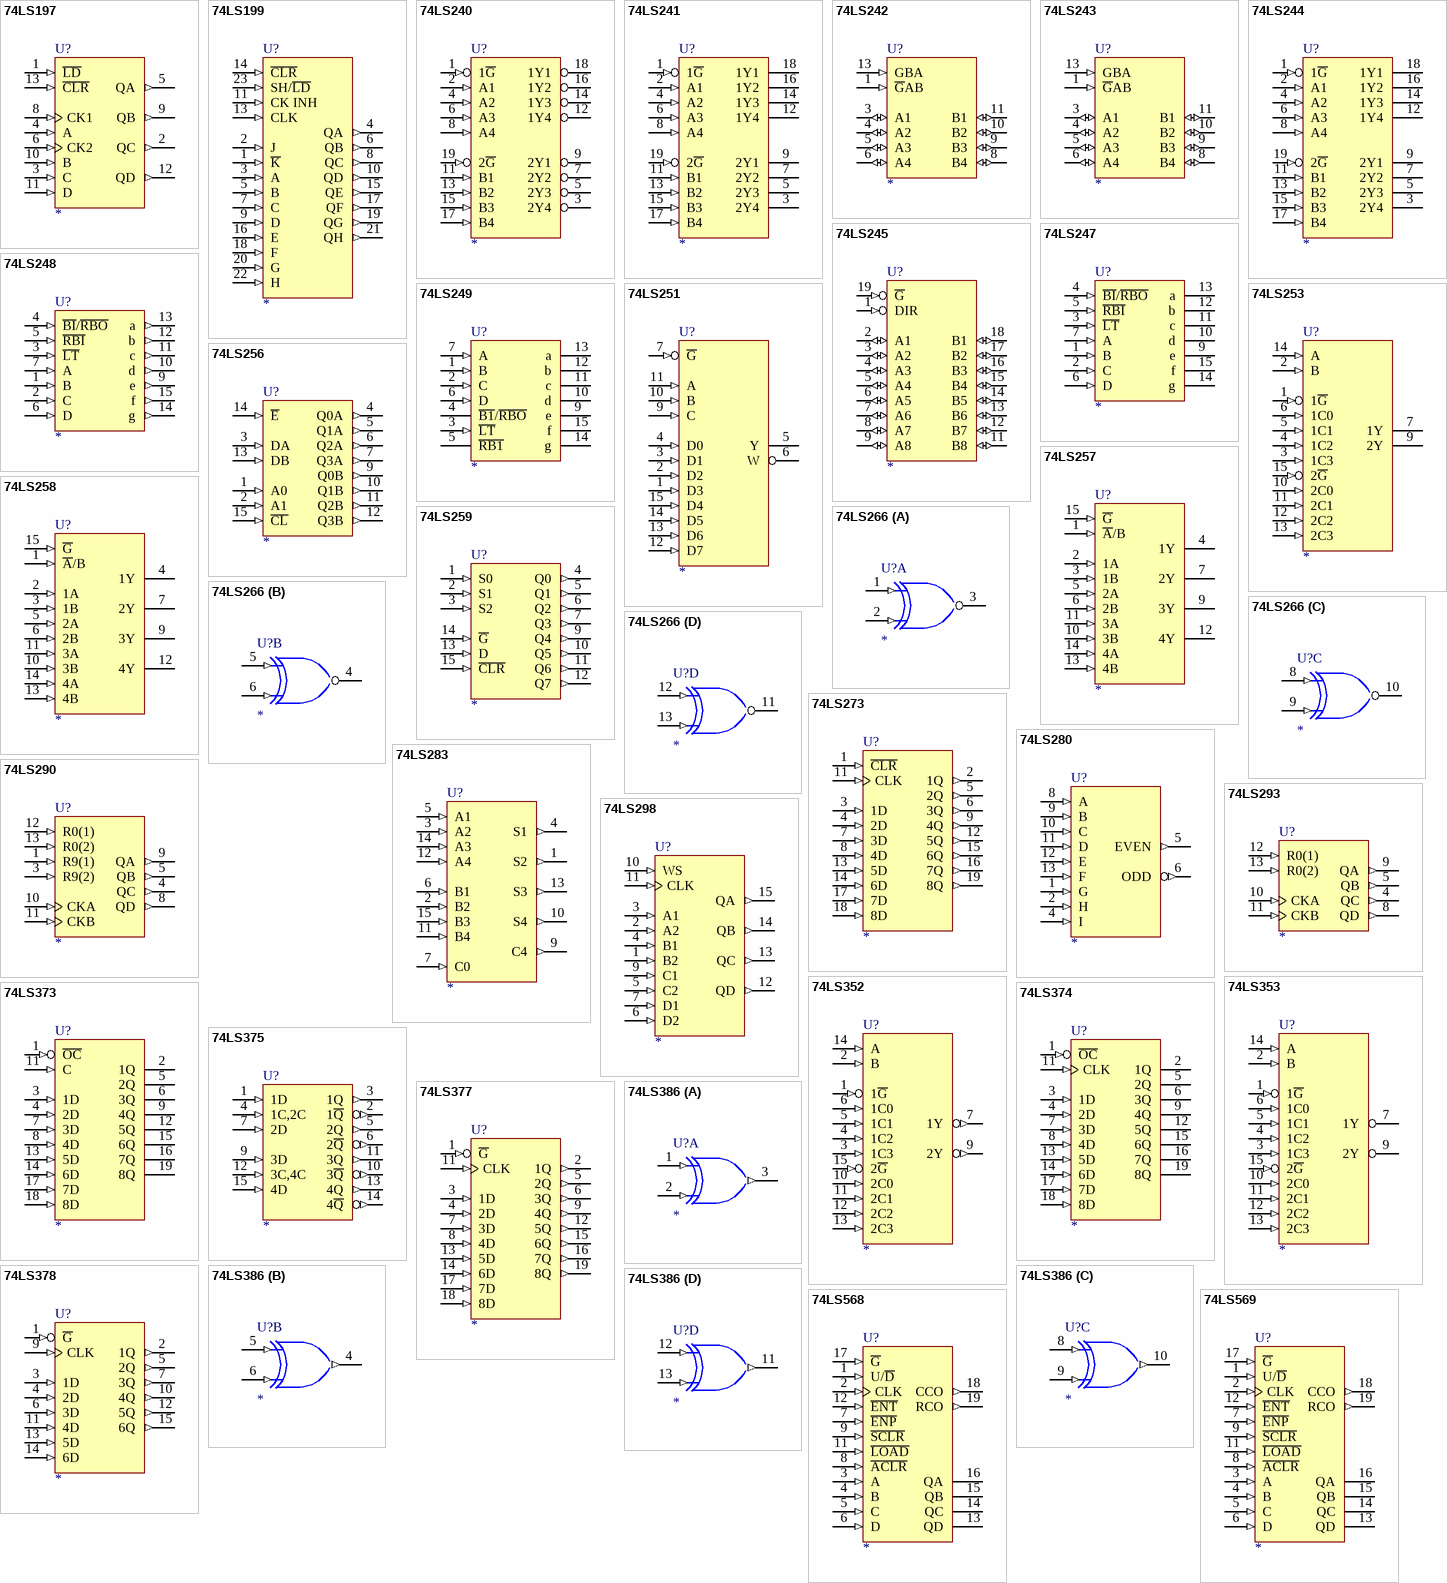
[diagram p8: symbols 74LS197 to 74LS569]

## 74LS197
designator U?
30-MHz Presettable Binary Counter/Latch
footprint DIP-14
simulation model 74LS197 (SIMCODE)
pins: 1 ~{LD} (in), 2 QC (out), 3 C (in), 4 A (in), 5 QA (out), 6 CK2 (in), 7 GND (power) hidden to GND, 8 CK1 (in), 9 QB (out), 10 B (in), 11 D (in), 12 QD (out), 13 ~{CLR} (in), 14 VCC (power) hidden to VCC
1 alternate drawing of the same symbol

## 74LS199
designator U?
8-Bit Shift Register
footprint DIP-24
simulation model 74LS199 (SIMCODE)
pins: 1 ~{K} (in), 2 J (in), 3 A (in), 4 QA (out), 5 B (in), 6 QB (out), 7 C (in), 8 QC (out), 9 D (in), 10 QD (out), 11 CK INH (in), 12 GND (power) hidden to GND, 13 CLK (in), 14 ~{CLR} (in), 15 QE (out), 16 E (in), 17 QF (out), 18 F (in), 19 QG (out), 20 G (in), 21 QH (out), 22 H (in), 23 SH/~{LD} (in), 24 VCC (power) hidden to VCC
1 alternate drawing of the same symbol

## 74LS240
designator U?
Octal Buffer and Line Driver with 3-State Output
footprint DIP-20
simulation model 74LS240 (SIMCODE)
pins: 1 1~{G} (in), 2 A1 (in), 3 2Y4 (hiz), 4 A2 (in), 5 2Y3 (hiz), 6 A3 (in), 7 2Y2 (hiz), 8 A4 (in), 9 2Y1 (hiz), 10 GND (power) hidden to GND, 11 B1 (in), 12 1Y4 (hiz), 13 B2 (in), 14 1Y3 (hiz), 15 B3 (in), 16 1Y2 (hiz), 17 B4 (in), 18 1Y1 (hiz), 19 2~{G} (in), 20 VCC (power) hidden to VCC
1 alternate drawing of the same symbol

## 74LS241
designator U?
Octal Buffer and Line Driver with 3-State Output
footprint DIP-20
simulation model 74LS241 (SIMCODE)
pins: 1 1~{G} (in), 2 A1 (in), 3 2Y4 (hiz), 4 A2 (in), 5 2Y3 (hiz), 6 A3 (in), 7 2Y2 (hiz), 8 A4 (in), 9 2Y1 (hiz), 10 GND (power) hidden to GND, 11 B1 (in), 12 1Y4 (hiz), 13 B2 (in), 14 1Y3 (hiz), 15 B3 (in), 16 1Y2 (hiz), 17 B4 (in), 18 1Y1 (hiz), 19 2~{G} (in), 20 VCC (power) hidden to VCC
1 alternate drawing of the same symbol

## 74LS242
designator U?
Quad Bus Transceiver
footprint DIP-14
simulation model 74LS242 (SIMCODE)
pins: 1 ~{G}AB (in), 3 A1 (io), 4 A2 (io), 5 A3 (io), 6 A4 (io), 7 GND (power) hidden to GND, 8 B4 (io), 9 B3 (io), 10 B2 (io), 11 B1 (io), 13 GBA (in), 14 VCC (power) hidden to VCC
1 alternate drawing of the same symbol

## 74LS243
designator U?
Quad Bus Transceiver
footprint DIP-14
simulation model 74LS243 (SIMCODE)
pins: 1 ~{G}AB (in), 3 A1 (io), 4 A2 (io), 5 A3 (io), 6 A4 (io), 7 GND (power) hidden to GND, 8 B4 (io), 9 B3 (io), 10 B2 (io), 11 B1 (io), 13 GBA (in), 14 VCC (power) hidden to VCC
1 alternate drawing of the same symbol

## 74LS244
designator U?
Octal Buffer and Line Driver with 3-State Output
footprint DIP-20
simulation model 74LS244 (SIMCODE)
pins: 1 1~{G} (in), 2 A1 (in), 3 2Y4 (hiz), 4 A2 (in), 5 2Y3 (hiz), 6 A3 (in), 7 2Y2 (hiz), 8 A4 (in), 9 2Y1 (hiz), 10 GND (power) hidden to GND, 11 B1 (in), 12 1Y4 (hiz), 13 B2 (in), 14 1Y3 (hiz), 15 B3 (in), 16 1Y2 (hiz), 17 B4 (in), 18 1Y1 (hiz), 19 2~{G} (in), 20 VCC (power) hidden to VCC
1 alternate drawing of the same symbol

## 74LS245
designator U?
Octal Bus Transceiver with 3-State Output
footprint DIP-20
simulation model 74LS245 (SIMCODE)
pins: 1 DIR (in), 2 A1 (io), 3 A2 (io), 4 A3 (io), 5 A4 (io), 6 A5 (io), 7 A6 (io), 8 A7 (io), 9 A8 (io), 10 GND (power) hidden to GND, 11 B8 (io), 12 B7 (io), 13 B6 (io), 14 B5 (io), 15 B4 (io), 16 B3 (io), 17 B2 (io), 18 B1 (io), 19 ~{G} (in), 20 VCC (power) hidden to VCC
1 alternate drawing of the same symbol

## 74LS247
designator U?
BCD-to-Seven Segment Decoder/Driver
footprint DIP-16
simulation model 74LS247 (SIMCODE)
pins: 1 B (in), 2 C (in), 3 ~{LT} (in), 4 ~{BI}/~{RBO} (in), 5 ~{RBI} (in), 6 D (in), 7 A (in), 8 GND (power) hidden to GND, 9 e (oc), 10 d (oc), 11 c (oc), 12 b (oc), 13 a (oc), 14 g (oc), 15 f (oc), 16 VCC (power) hidden to VCC
1 alternate drawing of the same symbol

## 74LS248
designator U?
BCD-to-Seven Segment Decoder/Driver
footprint DIP-16
simulation model 74LS248 (SIMCODE)
pins: 1 B (in), 2 C (in), 3 ~{LT} (in), 4 ~{BI}/~{RBO} (in), 5 ~{RBI} (in), 6 D (in), 7 A (in), 8 GND (power) hidden to GND, 9 e (out), 10 d (out), 11 c (out), 12 b (out), 13 a (out), 14 g (out), 15 f (out), 16 VCC (power) hidden to VCC
1 alternate drawing of the same symbol

## 74LS249
designator U?
BCD-to-Seven Segment Decoder with Open-Collector Outputs
footprint DIP-16
simulation model 74LS249 (SIMCODE)
pins: 1 B (in), 2 C (in), 3 ~{LT} (in), 4 ~{B1}/~{RBO}, 5 ~{RB1}, 6 D (in), 7 A (in), 8 GND (power) hidden to GND, 9 e (oc), 10 d (oc), 11 c (oc), 12 b (oc), 13 a (oc), 14 g (oc), 15 f (oc), 16 VCC (power) hidden to VCC

## 74LS251
designator U?
1-of-8 Data Selectors/Multiplexers with 3-State Output
footprint DIP-16
simulation model 74LS251 (SIMCODE)
pins: 1 D3 (in), 2 D2 (in), 3 D1 (in), 4 D0 (in), 5 Y (hiz), 6 W (hiz), 7 ~{G} (in), 8 GND (power) hidden to GND, 9 C (in), 10 B (in), 11 A (in), 12 D7 (in), 13 D6 (in), 14 D5 (in), 15 D4 (in), 16 VCC (power) hidden to VCC
1 alternate drawing of the same symbol

## 74LS253
designator U?
Dual 4-Line to 1-Line Data Selector/Multiplexer with 3-State Output
footprint DIP-16
simulation model 74LS253 (SIMCODE)
pins: 1 1~{G} (in), 2 B (in), 3 1C3 (in), 4 1C2 (in), 5 1C1 (in), 6 1C0 (in), 7 1Y (hiz), 8 GND (power) hidden to GND, 9 2Y (hiz), 10 2C0 (in), 11 2C1 (in), 12 2C2 (in), 13 2C3 (in), 14 A (in), 15 2~{G} (in), 16 VCC (power) hidden to VCC
1 alternate drawing of the same symbol

## 74LS256
designator U?
Dual 4-Bit Addressable Latch
footprint DIP-16
simulation model 74LS256 (SIMCODE)
pins: 1 A0 (in), 2 A1 (in), 3 DA (in), 4 Q0A (out), 5 Q1A (out), 6 Q2A (out), 7 Q3A (out), 8 GND (power) hidden to GND, 9 Q0B (out), 10 Q1B (out), 11 Q2B (out), 12 Q3B (out), 13 DB (in), 14 ~{E} (in), 15 ~{CL} (in), 16 VCC (power) hidden to VCC

## 74LS257
designator U?
Quad 2-Line to 1-Line Data/Selector/Multiplexer with 3-State Output
footprint DIP-16
simulation model 74LS257 (SIMCODE)
pins: 1 ~{A}/B (in), 2 1A (in), 3 1B (in), 4 1Y (hiz), 5 2A (in), 6 2B (in), 7 2Y (hiz), 8 GND (power) hidden to GND, 9 3Y (hiz), 10 3B (in), 11 3A (in), 12 4Y (hiz), 13 4B (in), 14 4A (in), 15 ~{G} (in), 16 VCC (power) hidden to VCC
1 alternate drawing of the same symbol

## 74LS258
designator U?
Quad 2-Line to 1-Line Data/Selector/Multiplexer with 3-State Output
footprint DIP-16
simulation model 74LS258 (SIMCODE)
pins: 1 ~{A}/B (in), 2 1A (in), 3 1B (in), 4 1Y (hiz), 5 2A (in), 6 2B (in), 7 2Y (hiz), 8 GND (power) hidden to GND, 9 3Y (hiz), 10 3B (in), 11 3A (in), 12 4Y (hiz), 13 4B (in), 14 4A (in), 15 ~{G} (in), 16 VCC (power) hidden to VCC
1 alternate drawing of the same symbol

## 74LS259
designator U?
8-Bit Addressable Latch
footprint DIP-16
simulation model 74LS259 (SIMCODE)
pins: 1 S0 (in), 2 S1 (in), 3 S2 (in), 4 Q0 (out), 5 Q1 (out), 6 Q2 (out), 7 Q3 (out), 8 GND (power) hidden to GND, 9 Q4 (out), 10 Q5 (out), 11 Q6 (out), 12 Q7 (out), 13 D (in), 14 ~{G} (in), 15 ~{CLR} (in), 16 VCC (power) hidden to VCC
1 alternate drawing of the same symbol

## 74LS266
designator U?
Quad Exclusive-NOR Gate with Open-Collector Output
footprint DIP-14
simulation model 74LS266 (SIMCODE)
part A pins: 1 A (in), 2 B (in), 3 Y (oc), 7 GND (power) hidden to GND, 14 VDD (power) hidden to VDD
part B pins: 4 Y (oc), 5 A (in), 6 B (in), 7 GND (power) hidden to GND, 14 VDD (power) hidden to VDD
part C pins: 7 GND (power) hidden to GND, 8 A (in), 9 B (in), 10 Y (oc), 14 VDD (power) hidden to VDD
part D pins: 7 GND (power) hidden to GND, 11 Y (oc), 12 A (in), 13 B (in), 14 VDD (power) hidden to VDD
1 alternate drawing of the same symbol

## 74LS273
designator U?
Octal D-Type Flip-Flop with Clear
footprint DIP-20
simulation model 74LS273 (SIMCODE)
pins: 1 ~{CLR} (in), 2 1Q (out), 3 1D (in), 4 2D (in), 5 2Q (out), 6 3Q (out), 7 3D (in), 8 4D (in), 9 4Q (out), 10 GND (power) hidden to GND, 11 CLK (in), 12 5Q (out), 13 5D (in), 14 6D (in), 15 6Q (out), 16 7Q (out), 17 7D (in), 18 8D (in), 19 8Q (out), 20 VCC (power) hidden to VCC
1 alternate drawing of the same symbol

## 74LS280
designator U?
9-Bit Odd/Even Parity Generator/Checker
footprint DIP-14
simulation model 74LS280 (SIMCODE)
pins: 1 G (in), 2 H (in), 4 I (in), 5 EVEN (out), 6 ODD (out), 7 GND (power) hidden to GND, 8 A (in), 9 B (in), 10 C (in), 11 D (in), 12 E (in), 13 F (in), 14 VCC (power) hidden to VCC
1 alternate drawing of the same symbol

## 74LS283
designator U?
4-Bit Binary Full Adder with Fast Carry
footprint DIP-16
simulation model 74LS283 (SIMCODE)
pins: 1 S2 (out), 2 B2 (in), 3 A2 (in), 4 S1 (out), 5 A1 (in), 6 B1 (in), 7 C0 (in), 8 GND (power) hidden to GND, 9 C4 (out), 10 S4 (out), 11 B4 (in), 12 A4 (in), 13 S3 (out), 14 A3 (in), 15 B3 (in), 16 VCC (power) hidden to VCC
1 alternate drawing of the same symbol

## 74LS290
designator U?
Decade Counter
footprint DIP-14
simulation model 74LS290 (SIMCODE)
pins: 1 R9(1) (in), 3 R9(2) (in), 4 QC (out), 5 QB (out), 7 GND (power) hidden to GND, 8 QD (out), 9 QA (out), 10 CKA (in), 11 CKB (in), 12 R0(1) (in), 13 R0(2) (in), 14 VCC (power) hidden to VCC
1 alternate drawing of the same symbol

## 74LS293
designator U?
4-Bit Binary Counter
footprint DIP-14
simulation model 74LS293 (SIMCODE)
pins: 4 QC (out), 5 QB (out), 7 GND (power) hidden to GND, 8 QD (out), 9 QA (out), 10 CKA (in), 11 CKB (in), 12 R0(1) (in), 13 R0(2) (in), 14 VCC (power) hidden to VCC
1 alternate drawing of the same symbol

## 74LS298
designator U?
Quad 2-Input Multiplexer with Storage
footprint DIP-16
simulation model 74LS298 (SIMCODE)
pins: 1 B2 (in), 2 A2 (in), 3 A1 (in), 4 B1 (in), 5 C2 (in), 6 D2 (in), 7 D1 (in), 8 GND (power) hidden to GND, 9 C1 (in), 10 WS (in), 11 CLK (in), 12 QD (out), 13 QC (out), 14 QB (out), 15 QA (out), 16 VCC (power) hidden to VCC
1 alternate drawing of the same symbol

## 74LS352
designator U?
Dual 4-Line to 1-Line Data Selector/Multiplexer
footprint DIP-16
simulation model 74LS352 (SIMCODE)
pins: 1 1~{G} (in), 2 B (in), 3 1C3 (in), 4 1C2 (in), 5 1C1 (in), 6 1C0 (in), 7 1Y (out), 8 GND (power) hidden to GND, 9 2Y (out), 10 2C0 (in), 11 2C1 (in), 12 2C2 (in), 13 2C3 (in), 14 A (in), 15 2~{G} (in), 16 VCC (power) hidden to VCC
1 alternate drawing of the same symbol

## 74LS353
designator U?
Dual 4-Line to 1-Line Data Selector/Multiplexer with 3-State Output
footprint DIP-16
simulation model 74LS353 (SIMCODE)
pins: 1 1~{G} (in), 2 B (in), 3 1C3 (in), 4 1C2 (in), 5 1C1 (in), 6 1C0 (in), 7 1Y (hiz), 8 GND (power) hidden to GND, 9 2Y (hiz), 10 2C0 (in), 11 2C1 (in), 12 2C2 (in), 13 2C3 (in), 14 A (in), 15 2~{G} (in), 16 VCC (power) hidden to VCC
1 alternate drawing of the same symbol

## 74LS373
designator U?
Octal D-Type Transparent Latch with 3-State Output
footprint DIP-20
simulation model 74LS373 (SIMCODE)
pins: 1 ~{OC} (in), 2 1Q (hiz), 3 1D (in), 4 2D (in), 5 2Q (hiz), 6 3Q (hiz), 7 3D (in), 8 4D (in), 9 4Q (hiz), 10 GND (power) hidden to GND, 11 C (in), 12 5Q (hiz), 13 5D (in), 14 6D (in), 15 6Q (hiz), 16 7Q (hiz), 17 7D (in), 18 8D (in), 19 8Q (hiz), 20 VCC (power) hidden to VCC
1 alternate drawing of the same symbol

## 74LS374
designator U?
Octal D-Type Edge-Triggered Flip-Flop with 3-State Output
footprint DIP-20
simulation model 74LS374 (SIMCODE)
pins: 1 ~{OC} (in), 2 1Q (hiz), 3 1D (in), 4 2D (in), 5 2Q (hiz), 6 3Q (hiz), 7 3D (in), 8 4D (in), 9 4Q (hiz), 10 GND (power) hidden to GND, 11 CLK (in), 12 5Q (hiz), 13 5D (in), 14 6D (in), 15 6Q (hiz), 16 7Q (hiz), 17 7D (in), 18 8D (in), 19 8Q (hiz), 20 VCC (power) hidden to VCC
1 alternate drawing of the same symbol

## 74LS375
designator U?
4-Bit Bistable Latch
footprint DIP-16
simulation model 74LS375 (SIMCODE)
pins: 1 1D (in), 2 1~{Q} (out), 3 1Q (out), 4 1C,2C (in), 5 2Q (out), 6 2~{Q} (out), 7 2D (in), 8 GND (power) hidden to GND, 9 3D (in), 10 3~{Q} (out), 11 3Q (out), 12 3C,4C (in), 13 4Q (out), 14 4~{Q} (out), 15 4D (in), 16 VCC (power) hidden to VCC
1 alternate drawing of the same symbol

## 74LS377
designator U?
Octal D-Type Flip-Flop with Enable
footprint DIP-20
simulation model 74LS377 (SIMCODE)
pins: 1 ~{G} (in), 2 1Q (out), 3 1D (in), 4 2D (in), 5 2Q (out), 6 3Q (out), 7 3D (in), 8 4D (in), 9 4Q (out), 10 GND (power) hidden to GND, 11 CLK (in), 12 5Q (out), 13 5D (in), 14 6D (in), 15 6Q (out), 16 7Q (out), 17 7D (in), 18 8D (in), 19 8Q (out), 20 VCC (power) hidden to VCC
1 alternate drawing of the same symbol

## 74LS378
designator U?
Hex D-Type Flip Flop with Enable
footprint DIP-16
simulation model 74LS378 (SIMCODE)
pins: 1 ~{G} (in), 2 1Q (out), 3 1D (in), 4 2D (in), 5 2Q (out), 6 3D (in), 7 3Q (out), 8 GND (power) hidden to GND, 9 CLK (in), 10 4Q (out), 11 4D (in), 12 5Q (out), 13 5D (in), 14 6D (in), 15 6Q (out), 16 VCC (power) hidden to VCC
1 alternate drawing of the same symbol

## 74LS386
designator U?
Quad Exclusive-OR Gate
footprint DIP-14
simulation model 74LS386 (SIMCODE)
part A pins: 1 A (in), 2 B (in), 3 Y (out), 7 GND (power) hidden to GND, 14 VCC (power) hidden to VCC
part B pins: 4 Y (out), 5 A (in), 6 B (in), 7 GND (power) hidden to GND, 14 VCC (power) hidden to VCC
part C pins: 7 GND (power) hidden to GND, 8 A (in), 9 B (in), 10 Y (out), 14 VCC (power) hidden to VCC
part D pins: 7 GND (power) hidden to GND, 11 Y (out), 12 A (in), 13 B (in), 14 VCC (power) hidden to VCC
1 alternate drawing of the same symbol

## 74LS568
designator U?
Synchronous 4-Bit Up/Down Decade Counter with 3-State Outputs
footprint DIP-20
simulation model 74LS568 (SIMCODE)
pins: 1 U/~{D} (in), 2 CLK (in), 3 A (in), 4 B (in), 5 C (in), 6 D (in), 7 ~{ENP} (in), 8 ~{ACLR} (in), 9 ~{SCLR} (in), 10 GND (power) hidden to GND, 11 ~{LOAD} (in), 12 ~{ENT} (in), 13 QD (hiz), 14 QC (hiz), 15 QB (hiz), 16 QA (hiz), 17 ~{G} (in), 18 CCO (out), 19 RCO (out), 20 VCC (power) hidden to VCC
1 alternate drawing of the same symbol

## 74LS569
designator U?
Synchronous 4-Bit Up/Down Binary Counter with 3-State Outputs
footprint DIP-20
simulation model 74LS569 (SIMCODE)
pins: 1 U/~{D} (in), 2 CLK (in), 3 A (in), 4 B (in), 5 C (in), 6 D (in), 7 ~{ENP} (in), 8 ~{ACLR} (in), 9 ~{SCLR} (in), 10 GND (power) hidden to GND, 11 ~{LOAD} (in), 12 ~{ENT} (in), 13 QD (hiz), 14 QC (hiz), 15 QB (hiz), 16 QA (hiz), 17 ~{G} (in), 18 CCO (out), 19 RCO (out), 20 VCC (power) hidden to VCC
1 alternate drawing of the same symbol

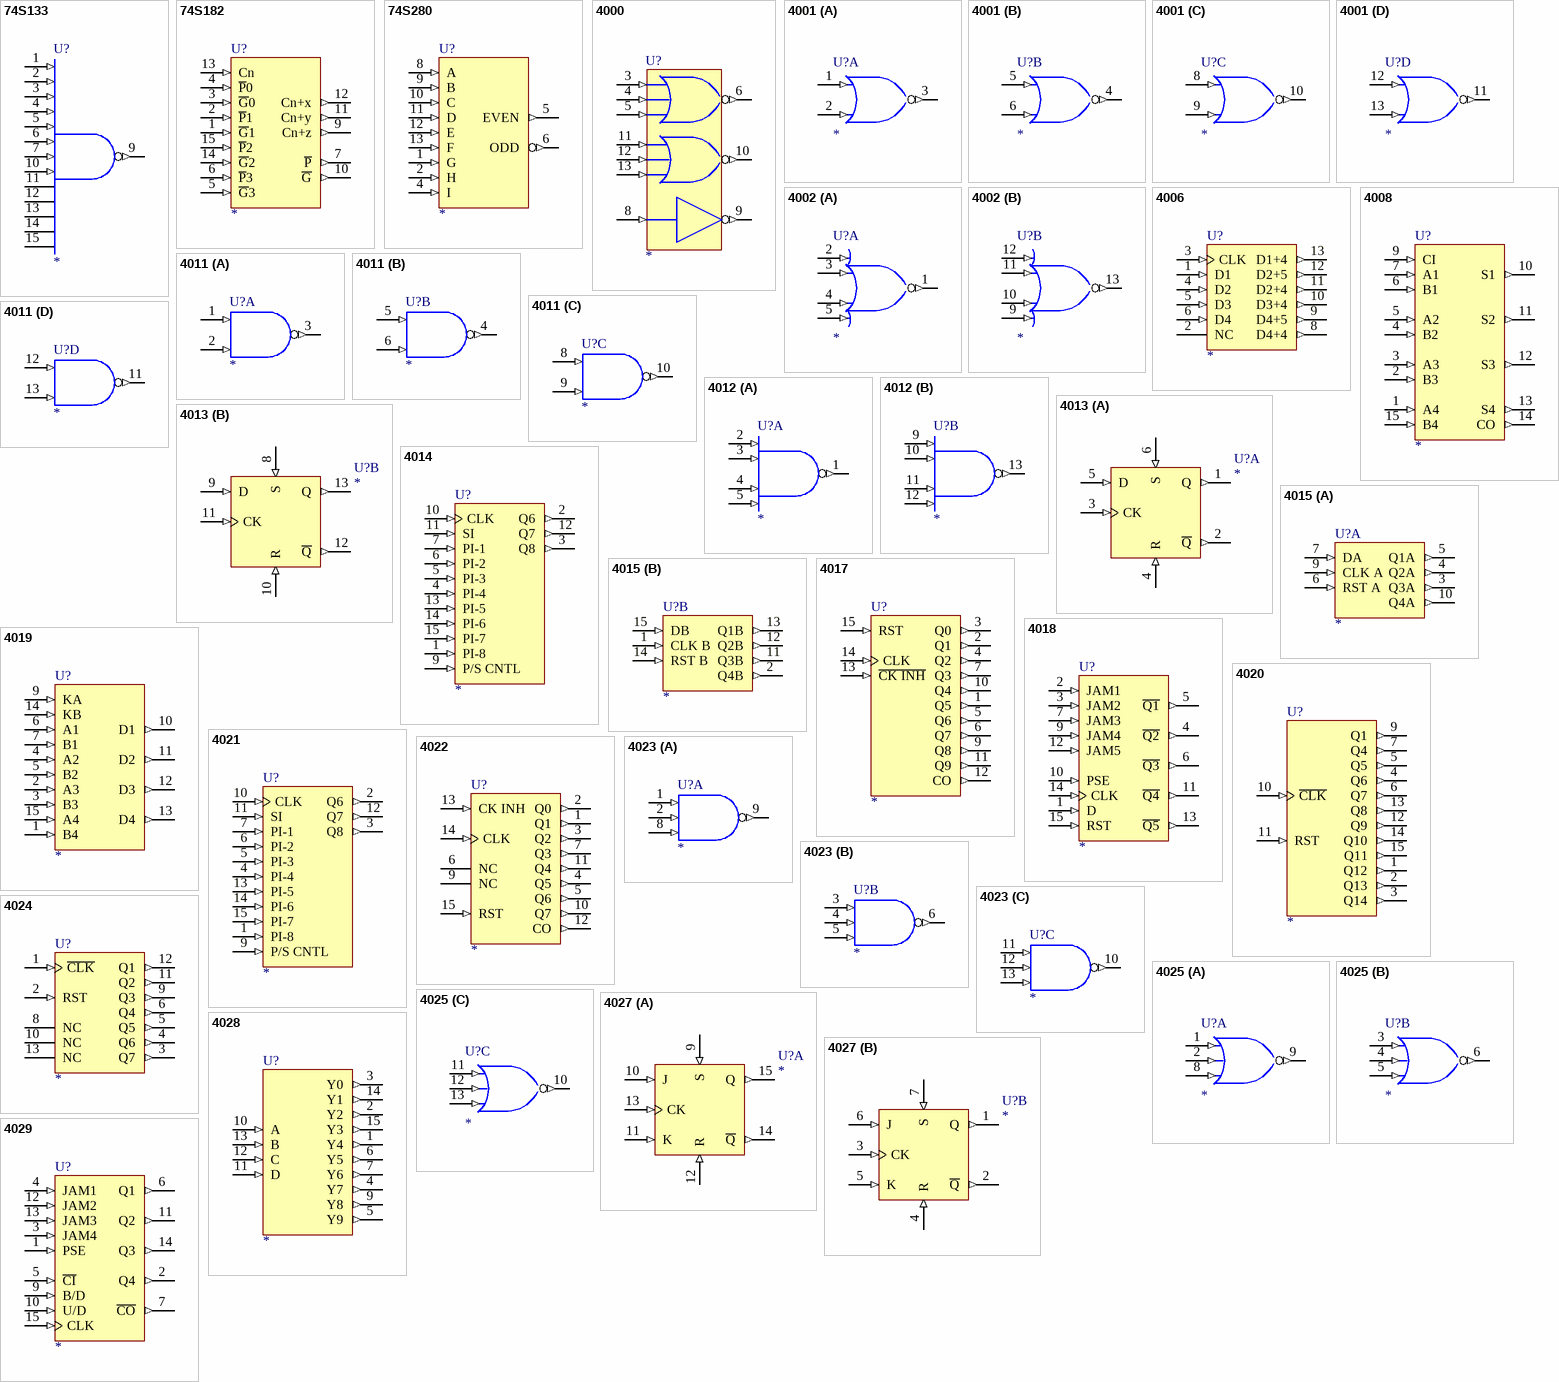
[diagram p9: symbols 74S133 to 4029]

## 74S133
designator U?
13-Input Positive-NAND Gate
footprint DIP-16
simulation model 74S133 (SIMCODE)
pins: 1 A (in), 2 B (in), 3 C (in), 4 D (in), 5 E (in), 6 F (in), 7 G (in), 8 GND (power) hidden to GND, 9 Y (out), 10 H (in), 11 I, 12 J, 13 K, 14 L, 15 M, 16 VCC (power) hidden to VCC
2 alternate drawings of the same symbol

## 74S182
designator U?
Look-Ahead Carry Generator
footprint DIP-16
simulation model 74S182 (SIMCODE)
pins: 1 ~{G}1 (in), 2 ~{P}1 (in), 3 ~{G}0 (in), 4 ~{P}0 (in), 5 ~{G}3 (in), 6 ~{P}3 (in), 7 ~{P} (out), 8 GND (power) hidden to GND, 9 Cn+z (out), 10 ~{G} (out), 11 Cn+y (out), 12 Cn+x (out), 13 Cn (in), 14 ~{G}2 (in), 15 ~{P}2 (in), 16 VCC (power) hidden to VCC
1 alternate drawing of the same symbol

## 74S280
designator U?
9-Bit Odd/Even Parity Generator/Checker
footprint DIP-14
simulation model 74S280 (SIMCODE)
pins: 1 G (in), 2 H (in), 4 I (in), 5 EVEN (out), 6 ODD (out), 7 GND (power) hidden to GND, 8 A (in), 9 B (in), 10 C (in), 11 D (in), 12 E (in), 13 F (in), 14 VCC (power) hidden to VCC
1 alternate drawing of the same symbol

## 4000
designator U?
Dual 3-Input NOR Gate plus Inverter
footprint DIP-14
simulation model 4000 (SIMCODE)
pins: 3 A (in), 4 B (in), 5 C (in), 6 Y (out), 7 GND (power) hidden to GND, 8 A (in), 9 Y (out), 10 Y (out), 11 A (in), 12 B (in), 13 C (in), 14 VDD (power) hidden to VDD
2 alternate drawings of the same symbol

## 4001
designator U?
Quad 2-Input NOR Gate
footprint DIP-14
simulation model 4001 (SIMCODE)
part A pins: 1 A (in), 2 B (in), 3 Y (out), 7 GND (power) hidden to GND, 14 VDD (power) hidden to VDD
part B pins: 4 Y (out), 5 A (in), 6 B (in), 7 GND (power) hidden to GND, 14 VDD (power) hidden to VDD
part C pins: 7 GND (power) hidden to GND, 8 A (in), 9 B (in), 10 Y (out), 14 VDD (power) hidden to VDD
part D pins: 7 GND (power) hidden to GND, 11 Y (out), 12 A (in), 13 B (in), 14 VDD (power) hidden to VDD
1 alternate drawing of the same symbol

## 4002
designator U?
Dual 4-Input NOR Gate
footprint DIP-14
simulation model 4002 (SIMCODE)
part A pins: 1 J (out), 2 A (in), 3 B (in), 4 C (in), 5 D (in), 7 GND (power) hidden to GND, 14 VDD (power) hidden to VDD
part B pins: 7 GND (power) hidden to GND, 9 E (in), 10 F (in), 11 G (in), 12 H (in), 13 K (out), 14 VDD (power) hidden to VDD
1 alternate drawing of the same symbol

## 4006
designator U?
18-Stage Static Shift Register
footprint DIP-14
simulation model 4006 (SIMCODE)
pins: 1 D1 (in), 2 NC, 3 CLK (in), 4 D2 (in), 5 D3 (in), 6 D4 (in), 7 GND (power) hidden to GND, 8 D4+4 (out), 9 D4+5 (out), 10 D3+4 (out), 11 D2+4 (out), 12 D2+5 (out), 13 D1+4 (out), 14 VDD (power) hidden to VDD

## 4008
designator U?
4-Bit Full Adder with Parallel Carry Output
footprint DIP-16
simulation model 4008 (SIMCODE)
pins: 1 A4 (in), 2 B3 (in), 3 A3 (in), 4 B2 (in), 5 A2 (in), 6 B1 (in), 7 A1 (in), 8 GND (power) hidden to GND, 9 CI (in), 10 S1 (out), 11 S2 (out), 12 S3 (out), 13 S4 (out), 14 CO (out), 15 B4 (in), 16 VDD (power) hidden to VDD
1 alternate drawing of the same symbol

## 4011
designator U?
Quad 2-Input NAND Gate
footprint DIP-14
simulation model 4011 (SIMCODE)
part A pins: 1 A (in), 2 B (in), 3 Y (out), 7 GND (power) hidden to GND, 14 VDD (power) hidden to VDD
part B pins: 4 Y (out), 5 A (in), 6 B (in), 7 GND (power) hidden to GND, 14 VDD (power) hidden to VDD
part C pins: 7 GND (power) hidden to GND, 8 A (in), 9 B (in), 10 Y (out), 14 VDD (power) hidden to VDD
part D pins: 7 GND (power) hidden to GND, 11 Y (out), 12 A (in), 13 B (in), 14 VDD (power) hidden to VDD

## 4012
designator U?
Dual 4-Input NAND Gate
footprint DIP-14
simulation model 4012 (SIMCODE)
part A pins: 1 Y (out), 2 A (in), 3 B (in), 4 C (in), 5 D (in), 7 GND (power) hidden to GND, 14 VDD (power) hidden to VDD
part B pins: 7 GND (power) hidden to GND, 9 A (in), 10 B (in), 11 C (in), 12 D (in), 13 Y (out), 14 VDD (power) hidden to VDD
2 alternate drawings of the same symbol

## 4013
designator U?
Dual D-Type Flip-Flop
footprint DIP-14
simulation model 4013 (SIMCODE)
part A pins: 1 Q (out), 2 ~{Q} (out), 3 CK (in), 4 R (in), 5 D (in), 6 S (in), 7 GND (power) hidden to GND, 14 VDD (power) hidden to VDD
part B pins: 7 GND (power) hidden to GND, 8 S (in), 9 D (in), 10 R (in), 11 CK (in), 12 ~{Q} (out), 13 Q (out), 14 VDD (power) hidden to VDD

## 4014
designator U?
8-Stage Shift Register (Synchronous Parallel or Serial Input/Serial Output)
footprint DIP-16
simulation model 4014 (SIMCODE)
pins: 1 PI-8 (in), 2 Q6 (out), 3 Q8 (out), 4 PI-4 (in), 5 PI-3 (in), 6 PI-2 (in), 7 PI-1 (in), 8 GND (power) hidden to GND, 9 P/S CNTL (in), 10 CLK (in), 11 SI (in), 12 Q7 (out), 13 PI-5 (in), 14 PI-6 (in), 15 PI-7 (in), 16 VDD (power) hidden to VDD

## 4015
designator U?
Dual 4-Stage Static Shift Register with Serial Input/Parallel Output
footprint DIP-16
simulation model 4015 (SIMCODE)
part A pins: 3 Q3A (out), 4 Q2A (out), 5 Q1A (out), 6 RST A (in), 7 DA (in), 8 GND (power) hidden to GND, 9 CLK A (in), 10 Q4A (out), 16 VDD (power) hidden to VDD
part B pins: 1 CLK B (in), 2 Q4B (out), 8 GND (power) hidden to GND, 11 Q3B (out), 12 Q2B (out), 13 Q1B (out), 14 RST B (in), 15 DB (in), 16 VDD (power) hidden to VDD

## 4017
designator U?
Decade Counter with 10 Decoded Outputs
footprint DIP-16
simulation model 4017 (SIMCODE)
pins: 1 Q5 (out), 2 Q1 (out), 3 Q0 (out), 4 Q2 (out), 5 Q6 (out), 6 Q7 (out), 7 Q3 (out), 8 GND (power) hidden to GND, 9 Q8 (out), 10 Q4 (out), 11 Q9 (out), 12 CO (out), 13 ~{CK INH} (in), 14 CLK (in), 15 RST (in), 16 VDD (power) hidden to VDD
1 alternate drawing of the same symbol

## 4018
designator U?
Presettable Divide-by-N Counter
footprint DIP-16
simulation model 4018 (SIMCODE)
pins: 1 D (in), 2 JAM1 (in), 3 JAM2 (in), 4 ~{Q2} (out), 5 ~{Q1} (out), 6 ~{Q3} (out), 7 JAM3 (in), 8 GND (power) hidden to GND, 9 JAM4 (in), 10 PSE (in), 11 ~{Q4} (out), 12 JAM5 (in), 13 ~{Q5} (out), 14 CLK (in), 15 RST (in), 16 VDD (power) hidden to VDD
